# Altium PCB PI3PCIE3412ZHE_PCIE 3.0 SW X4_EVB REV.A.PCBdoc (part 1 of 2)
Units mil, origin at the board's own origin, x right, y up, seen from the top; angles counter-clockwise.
Board outline 3399 x 2712 mil, 8 copper layers (TopLayer, InternalPlane1, MidLayer1, MidLayer2, MidLayer3, MidLayer4, InternalPlane2, BottomLayer); 24 components, 100 nets, 589 pads, 111 vias.
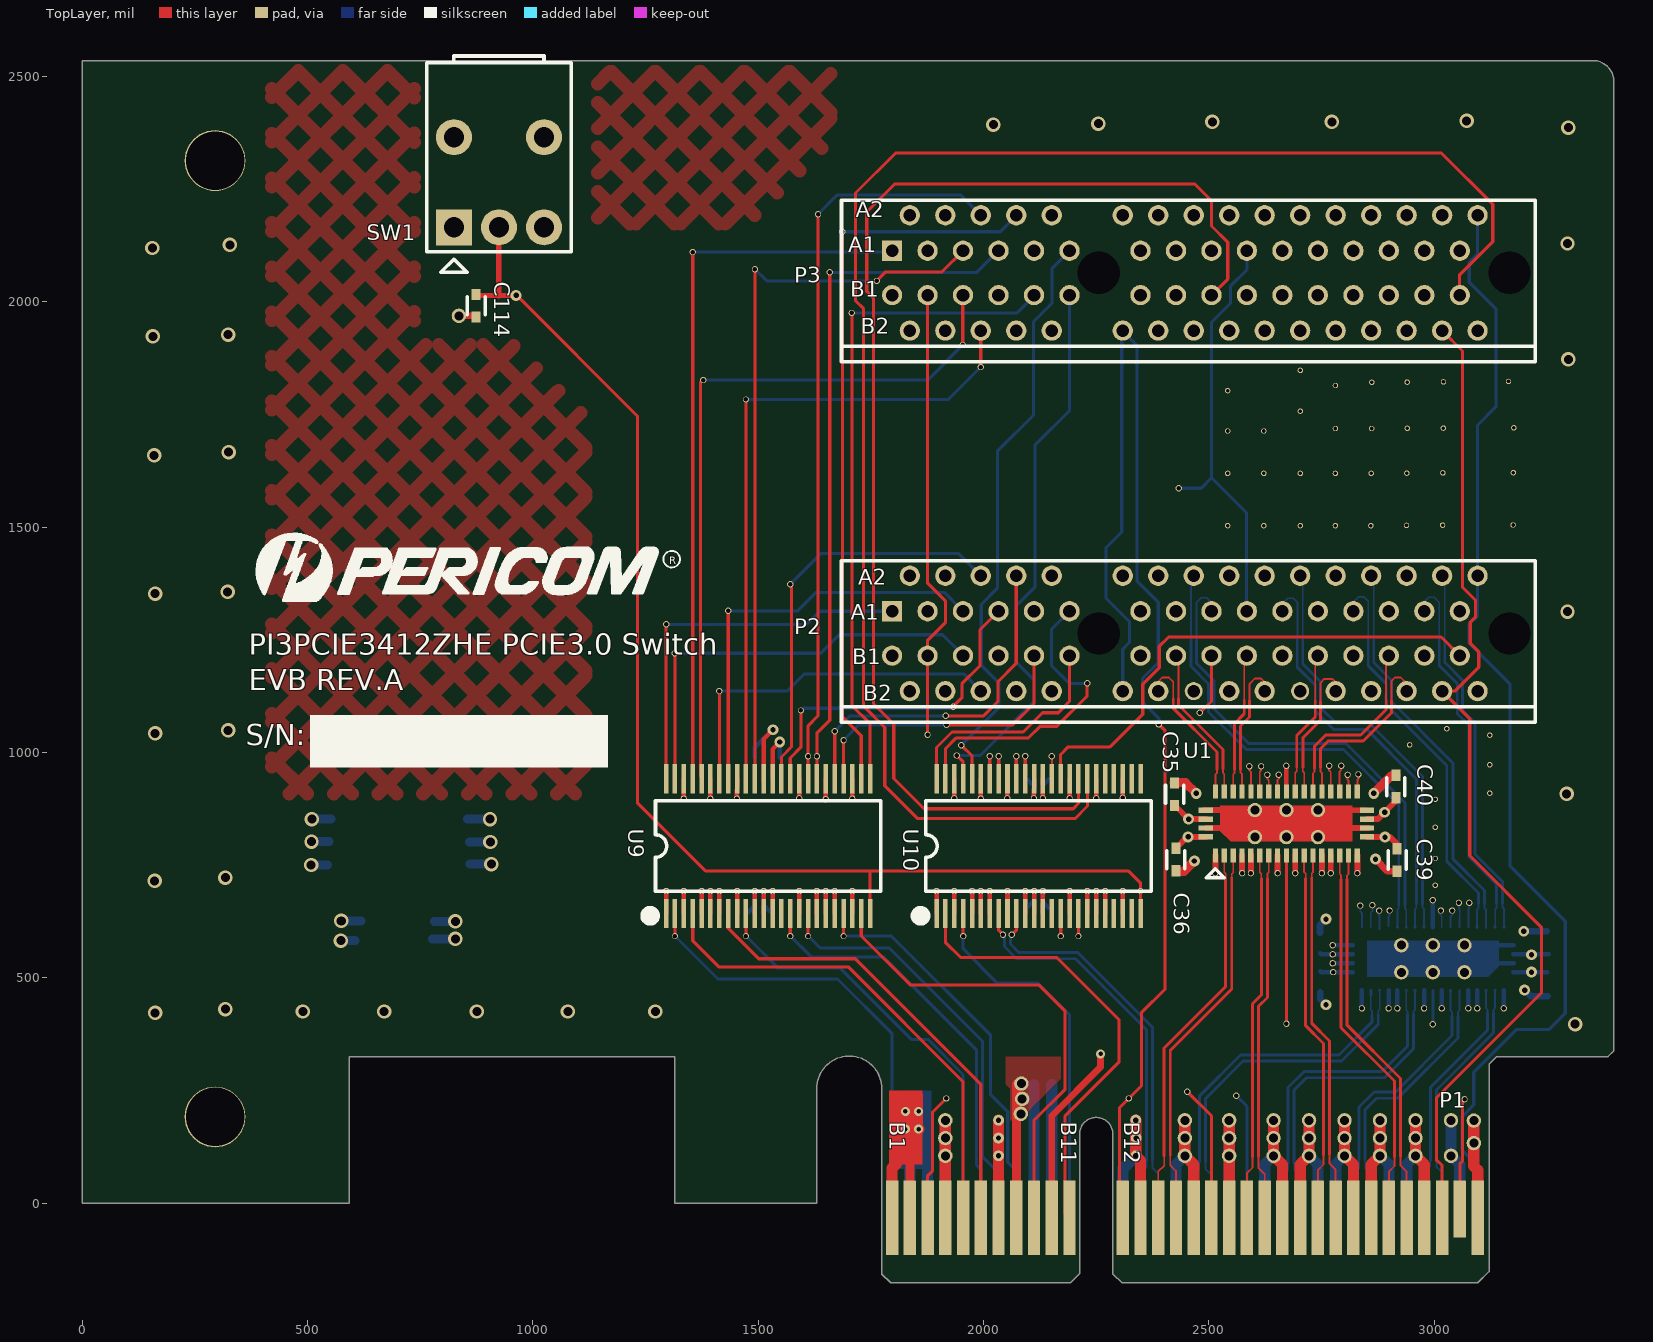
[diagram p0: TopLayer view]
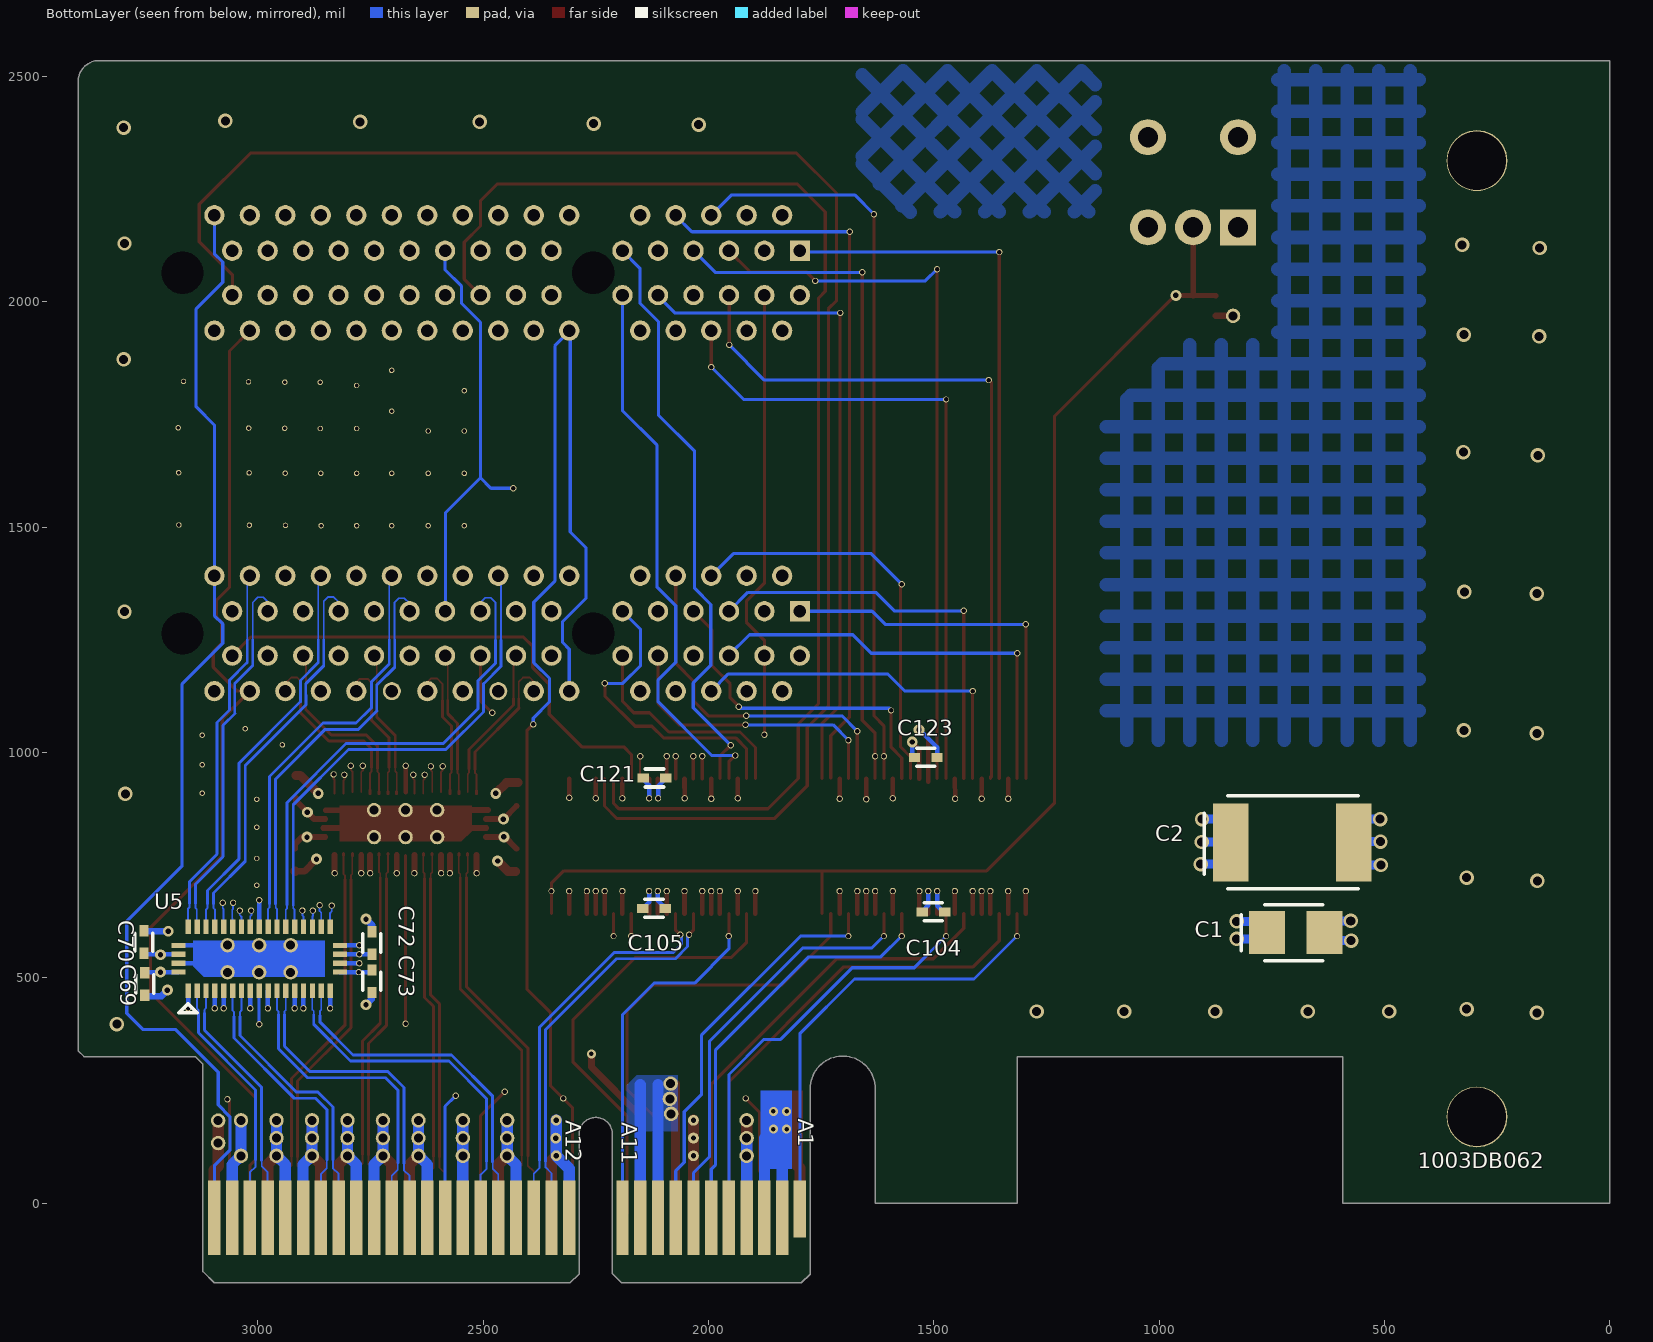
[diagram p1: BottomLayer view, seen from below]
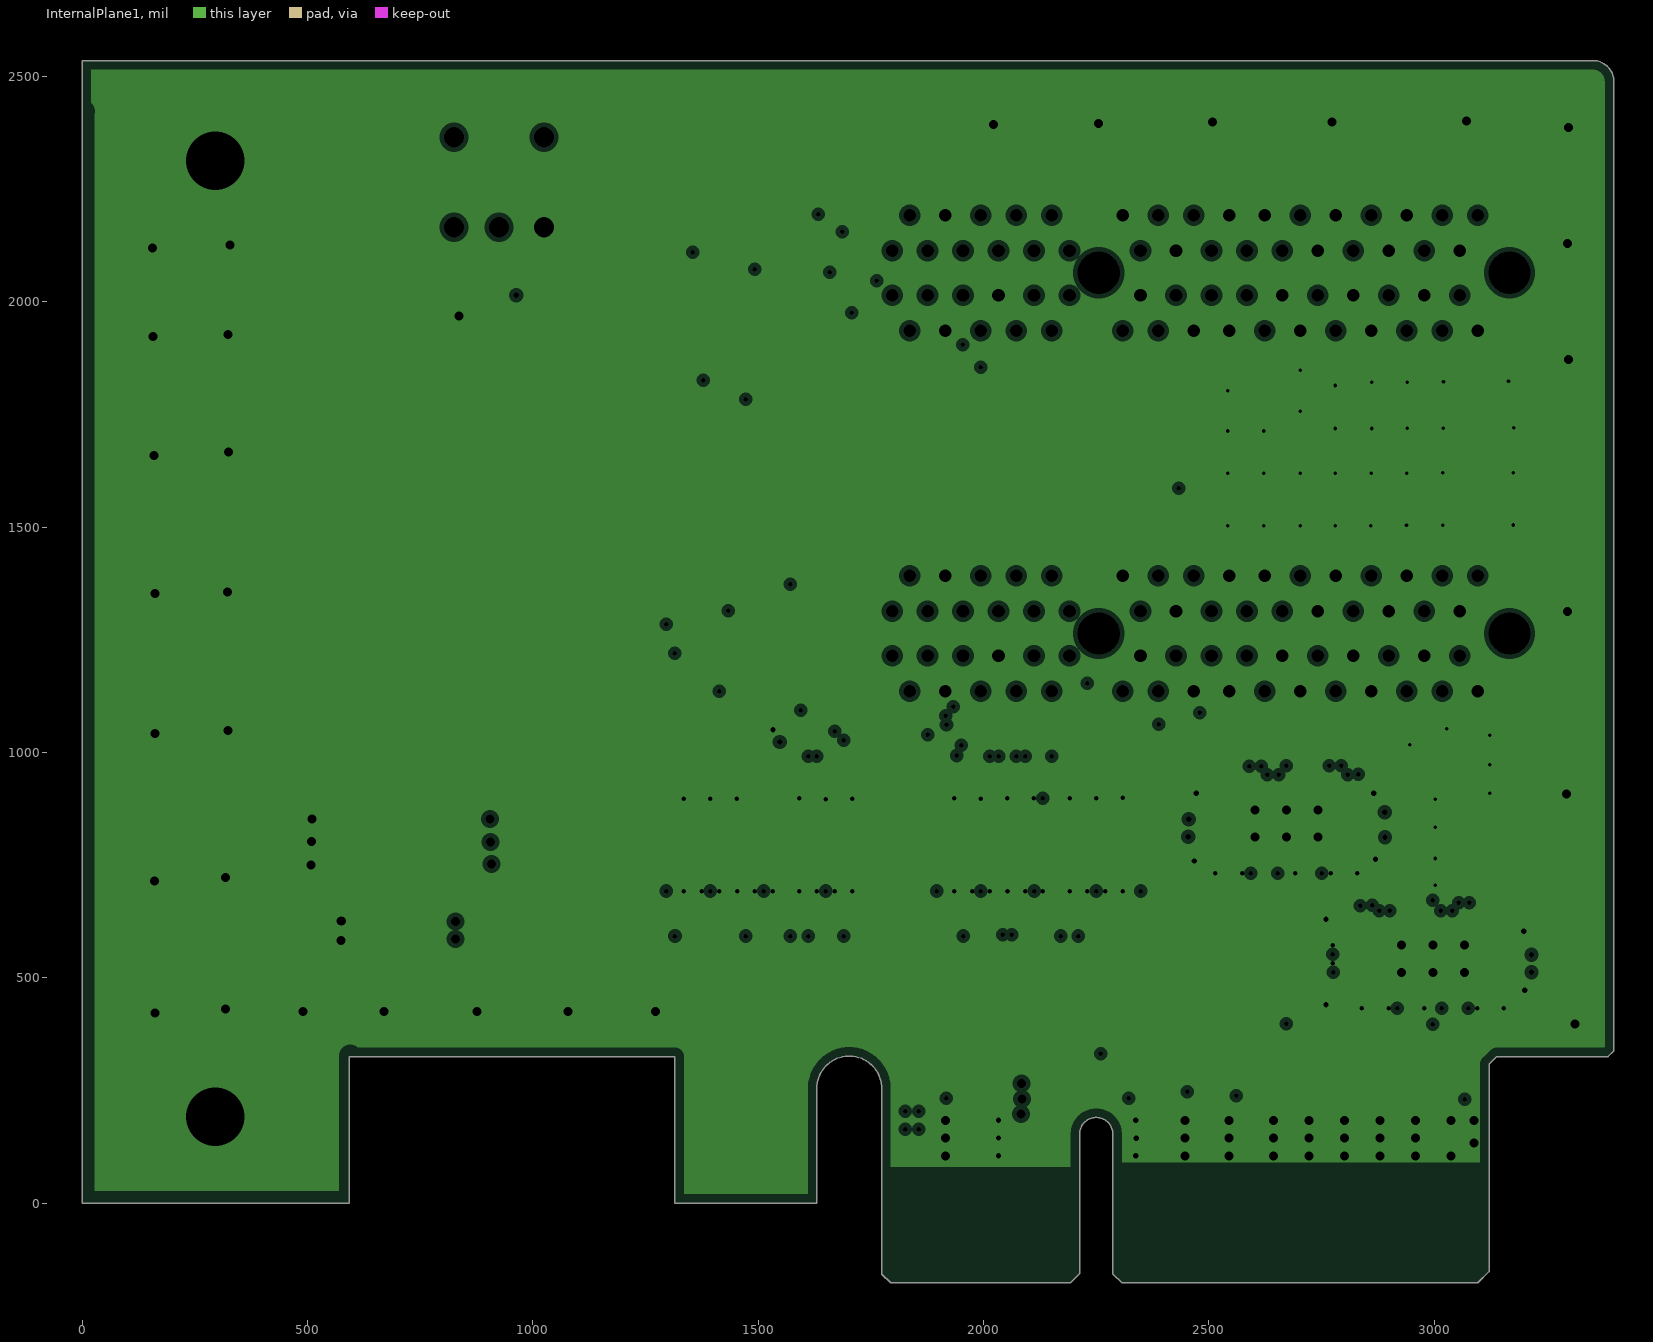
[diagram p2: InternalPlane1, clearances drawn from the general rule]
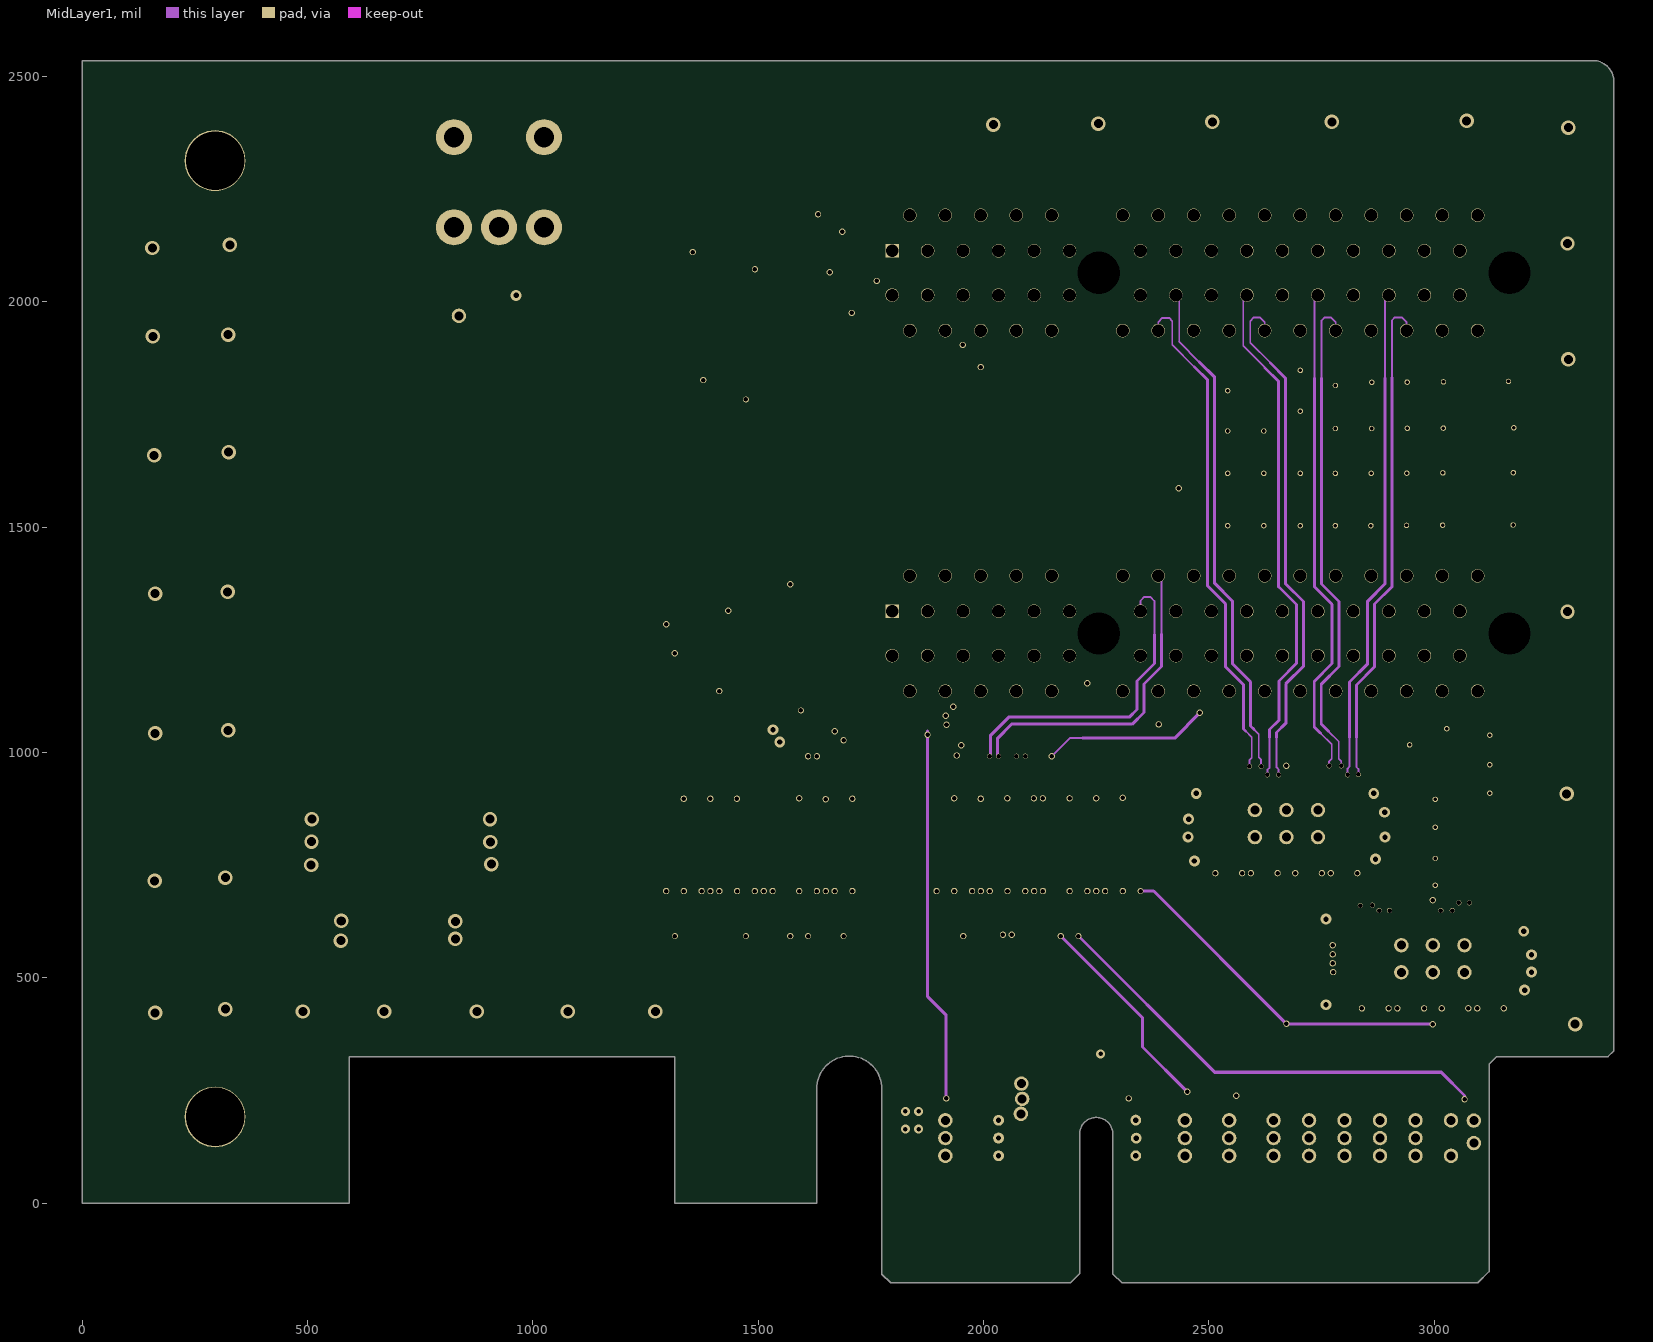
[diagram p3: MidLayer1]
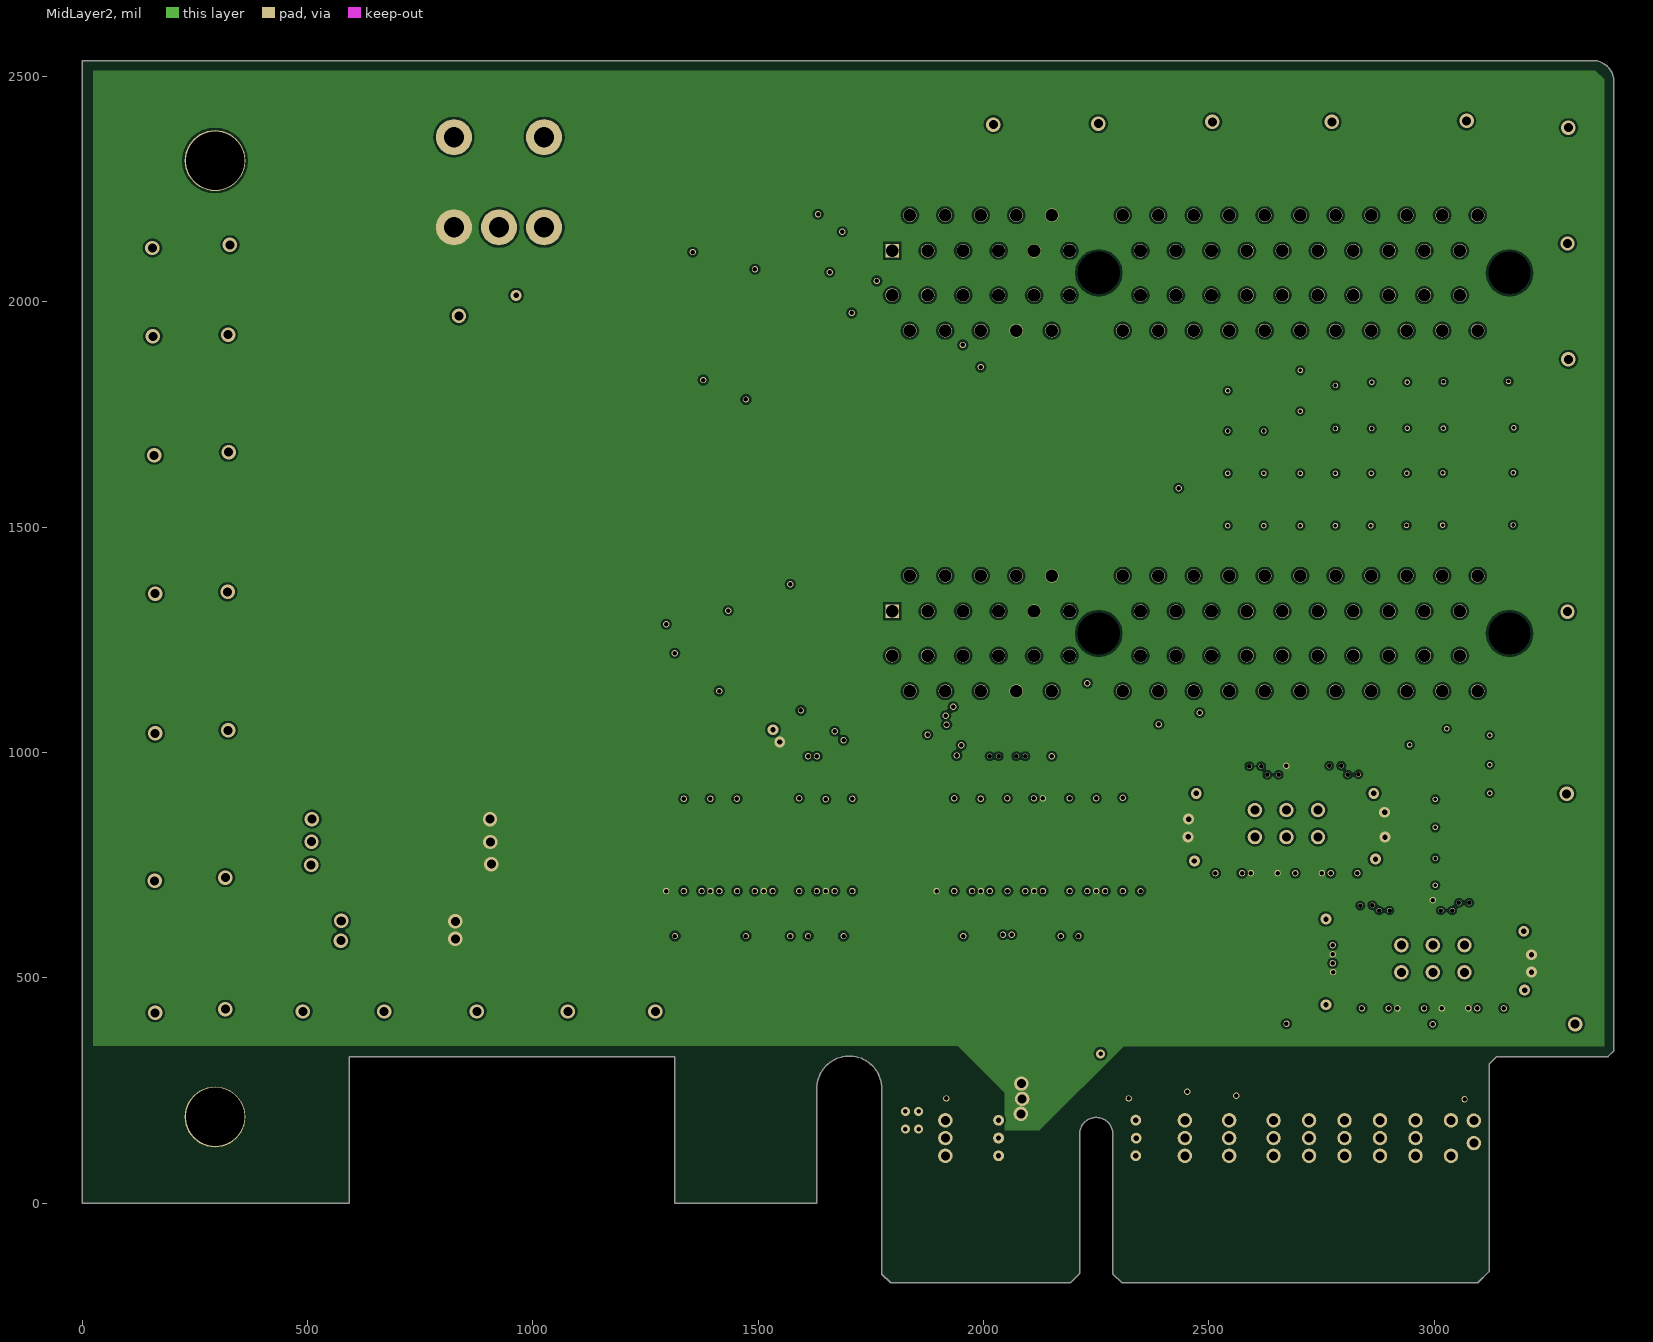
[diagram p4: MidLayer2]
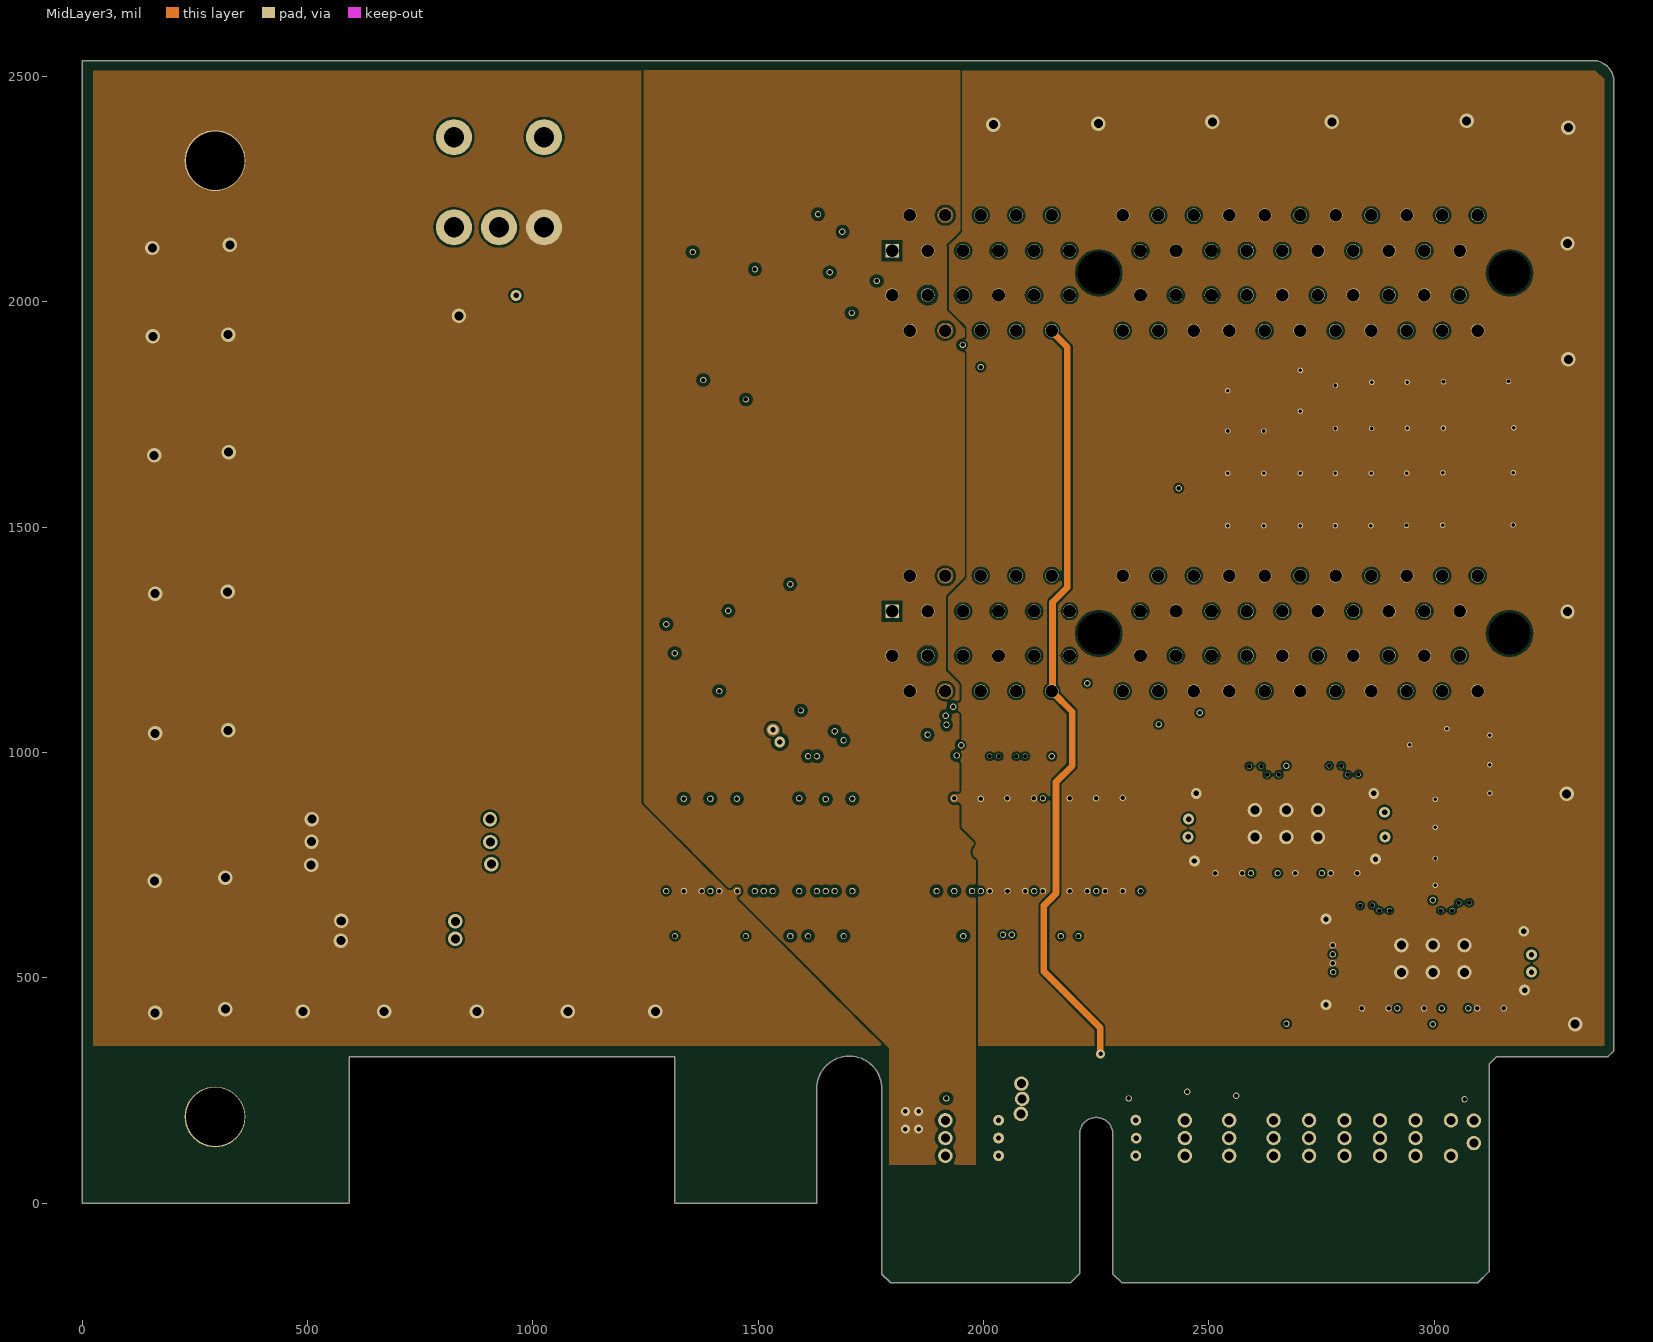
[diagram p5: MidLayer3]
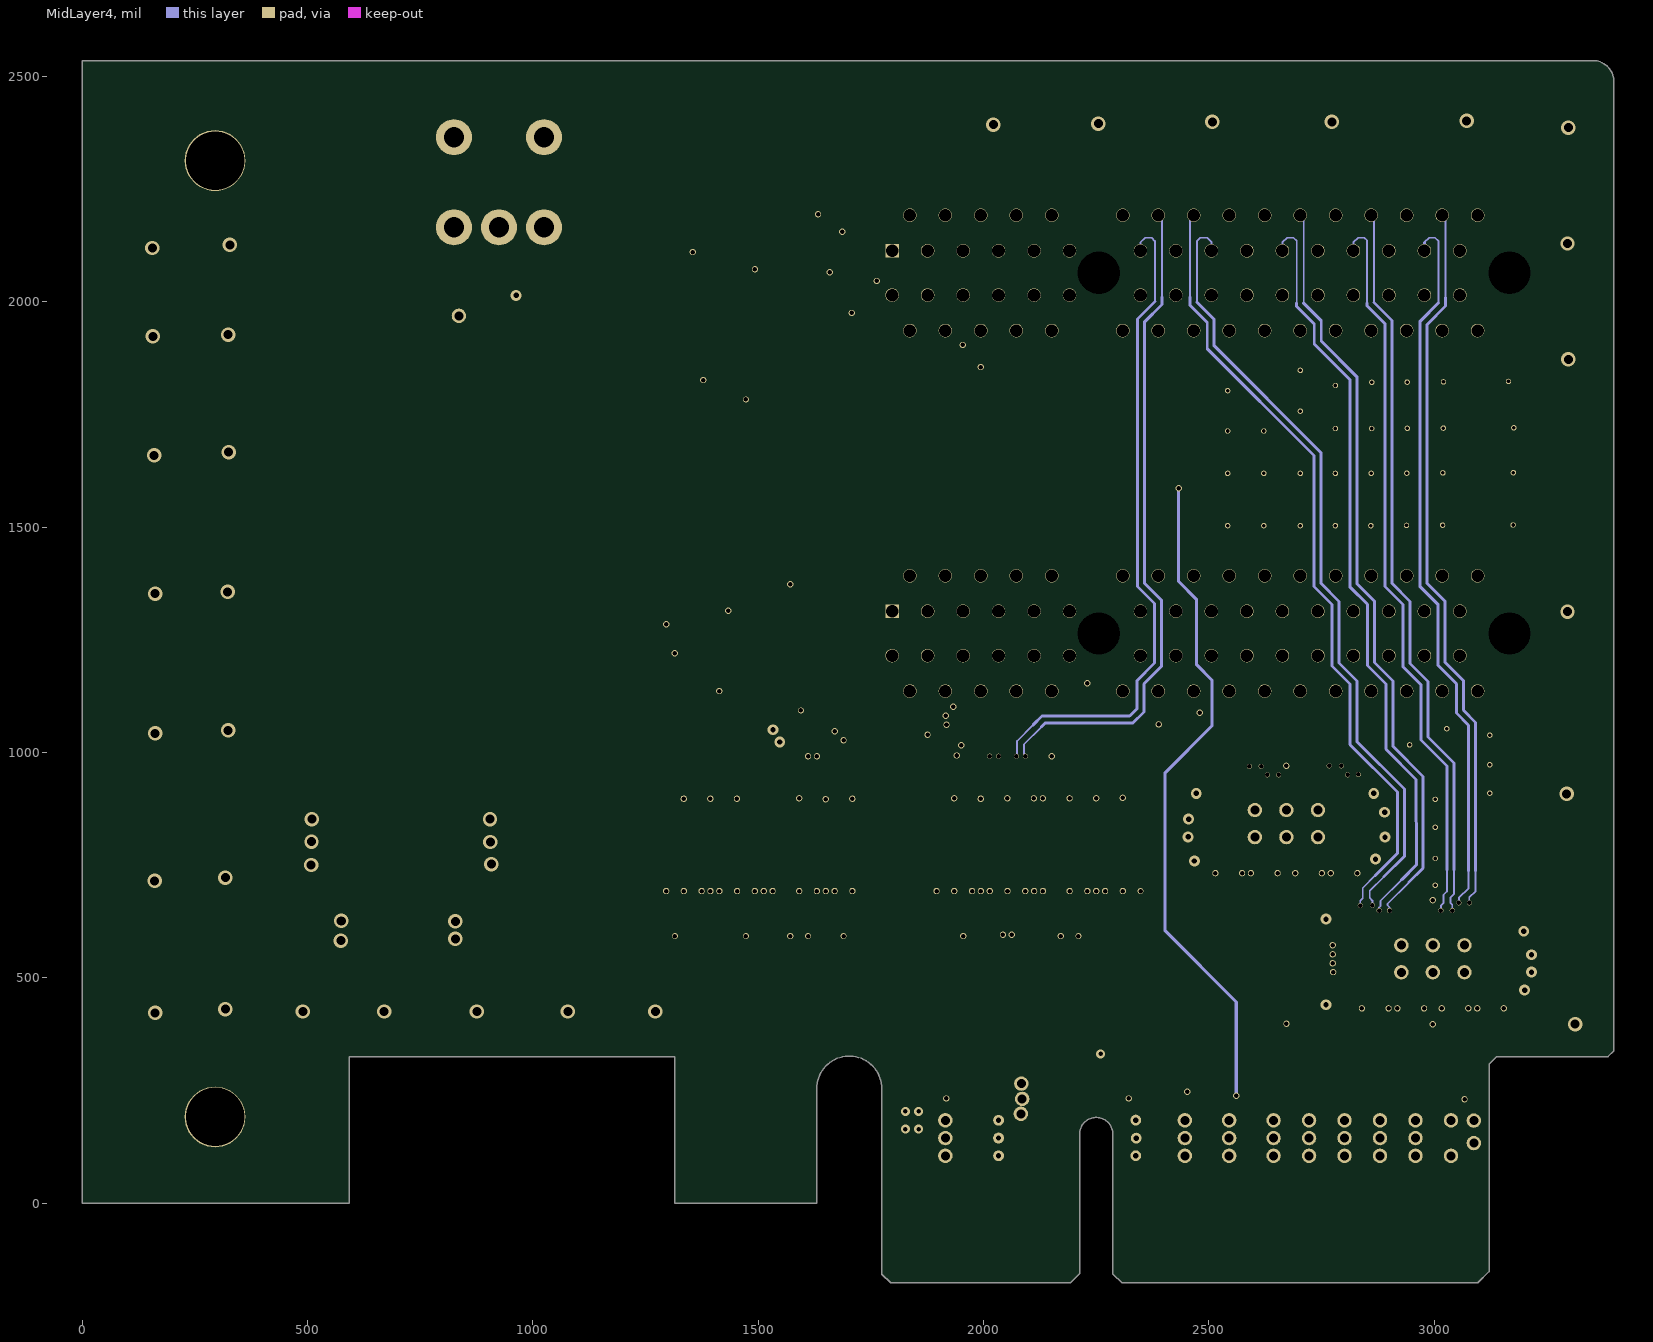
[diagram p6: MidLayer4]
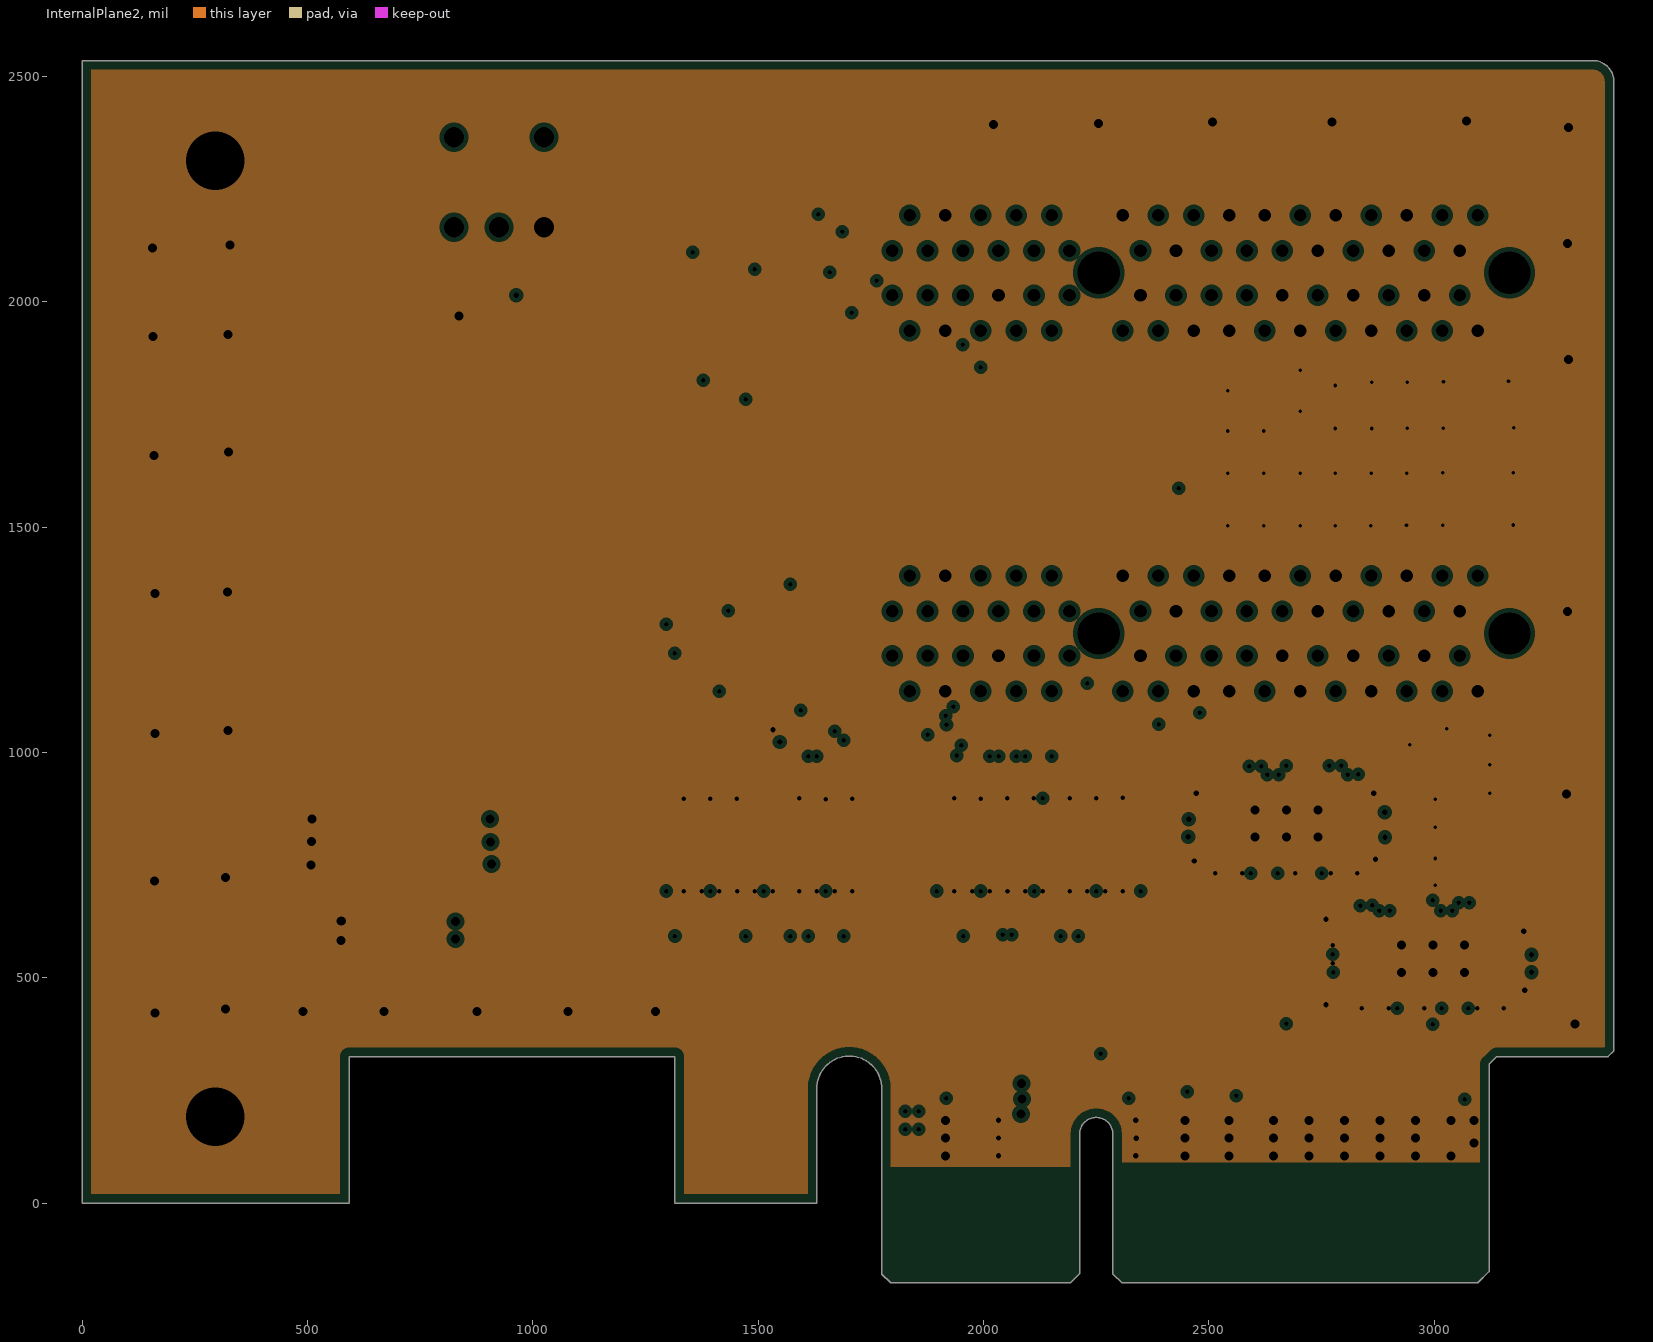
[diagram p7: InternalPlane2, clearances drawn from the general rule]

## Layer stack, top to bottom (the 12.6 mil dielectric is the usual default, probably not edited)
TopLayer: signal copper 1.4
Dielectric: core 12.6, FR-4, Dk 4.8
InternalPlane1: plane copper 1.4, net GND
Dielectric: prepreg 12.6, FR-4, Dk 4.8
MidLayer1: signal copper 1.4
Dielectric: core 12.6, FR-4, Dk 4.8
MidLayer2: signal copper 1.4
Dielectric: prepreg 12.6, FR-4, Dk 4.8
MidLayer3: signal copper 1.4
Dielectric: core 12.6, FR-4, Dk 4.8
MidLayer4: signal copper 1.4
Dielectric: prepreg 12.6, FR-4, Dk 4.8
InternalPlane2: plane copper 1.4, net GND
Dielectric: core 12.6, FR-4, Dk 4.8
BottomLayer: signal copper 1.4

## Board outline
1794.24,-177 1774.24,-158 1774.24,254 ccw(c1702.24,254) 1630.24,254 1630.24,0 1315.24,0 1315.24,325 592.24,325 592.24,0 0,0 0,2535 3353,2535 cw(c3352,2488) 3399,2487 3399,338 3385.99,324.99 3385.99,325 3139,325 3121.99,307.99 3121.99,-152 3122,-152 3097,-177 2307.24,-177 2287.24,-158 2287.24,153 ccw(c2250.24,153) 2213.24,153 2213.24,-157 2193.24,-177

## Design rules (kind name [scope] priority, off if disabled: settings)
Clearance [InNetClass('gap7')] p1: gap=5
Clearance Clearance_3 [OnLayer('BottomLayer') vs OnLayer('BottomLayer')] p2: gap=5.8
Clearance Clearance_2 [OnLayer('TopLayer') vs OnLayer('TopLayer')] p3: gap=5.8
Clearance Clearance_1 [All] p4: gap=5
ComponentClearance [All] p1: gap=10 collisioncheckmode=2 verticalgap=10
DiffPairsRouting [All] p1: maxlimit=6 minlimit=6 mostfreqgap=6 maxuncoupledlength=500
HoleSize [All] p1: absolutevalues=TRUE maxlimit=300 minlimit=1 maxpercent=80.000 minpercent=20.000
MatchedLengths MatchedLengths_1 [InNetClass('REFCLK') vs InFromToClass('')] p1: tolerance=50 checknetsindiffpair=TRUE checkdiffpairvsdiffpair=TRUE checkothers=TRUE
MatchedLengths [InNetClass('S_CLK') vs InFromToClass('')] p2: tolerance=50 checknetsindiffpair=TRUE checkdiffpairvsdiffpair=TRUE checkothers=TRUE
MinimumAnnularRing [All] p1 off: minimumring=0.5
PlaneClearance [All] p1: clearance=10
PlaneConnect PlaneConnect_2 [HasPad('Free-0')] p1: planeconnectstyle=Direct reliefexpansion=20 reliefentries=4 reliefconductorwidth=10 reliefairgap=10
PlaneConnect PlaneConnect_1 [HasPad('Free-998')] p2: planeconnectstyle=Direct reliefexpansion=20 reliefentries=4 reliefconductorwidth=10 reliefairgap=10
PlaneConnect PlaneConnect_3 [All] p3: planeconnectstyle=Direct reliefexpansion=20 reliefentries=4 reliefconductorwidth=10 reliefairgap=10
PlaneConnect [All] p4: planeconnectstyle=Direct reliefexpansion=10 reliefentries=4 reliefconductorwidth=12 reliefairgap=6
PolygonConnect [All] p1: connectstyle=Direct reliefconductorwidth=10 reliefentries=4 polygonreliefangle="90 Angle"
RoomDefinition "P05-PI3DBV40 SW" [InComponentClass('P05-PI3DBV40 SW')] p1: confinementstyle=ConfineIn formatcopy=TRUE lockcomponents=FALSE outline -6697.46,-11297.6 -4697.46,-11297.6 -4697.46,-10297.6 -6697.46,-10297.6
RoomDefinition "P04-PI3PCIE3412ZHE SW" [InComponentClass('P04-PI3PCIE3412ZHE SW')] p2: confinementstyle=ConfineIn formatcopy=TRUE lockcomponents=FALSE outline -6697.46,-11297.6 -4697.46,-11297.6 -4697.46,-10297.6 -6697.46,-10297.6
RoomDefinition P03-PCI_EXPRESS_CONNx4 [InComponentClass('P03-PCI_EXPRESS_CONNx4')] p3: confinementstyle=ConfineIn formatcopy=TRUE lockcomponents=FALSE outline -6697.46,-11297.6 -4697.46,-11297.6 -4697.46,-10297.6 -6697.46,-10297.6
RoomDefinition P02-PCI_EDGE_CONNx4 [InComponentClass('P02-PCI_EDGE_CONNx4')] p4: confinementstyle=ConfineIn formatcopy=TRUE lockcomponents=FALSE outline -6697.46,-11297.6 -4697.46,-11297.6 -4697.46,-10297.6 -6697.46,-10297.6
RoutingVias [All] p1: holewidth=28 width=50 viastyle="Through Hole" minholewidth=8 minwidth=10 maxholewidth=28 maxwidth=50
SolderMaskExpansion SolderMaskExpansion_2 [HasPad('Free-998')] p1: expansion=-6
SolderMaskExpansion SolderMaskExpansion_3 [HasPad('Free-0')] p2: expansion=-10
SolderMaskExpansion SolderMaskExpansion_1 [(IsWire) Or (IsVia) Or (IsFill)] p3: expansion=-6
SolderMaskExpansion [All] p4: expansion=2.5
TestPointUsage [All] p1: valid=0 allowmultiple=FALSE
Testpoint [All] p1: side=15 testpointundercomponent=TRUE minsize=40 maxsize=100 preferedsize=60 minholesize=20 maxholesize=40 preferedholesize=32 testpointgrid=1 style=1023 order=0123456789
UnRoutedNet UnRoutedNet_2 [All] p1:
Width [InNetClass('diff')] p1: maxlimit=50 minlimit=4 preferedwidth=6.5
Width Width_2 [InNetClass('PWR')] p2: maxlimit=50 minlimit=4 preferedwidth=10
Width Width_1 [All] p3: maxlimit=70 minlimit=4 preferedwidth=7
13 further rules are at their usual default settings.

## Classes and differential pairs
component class "P05-PI3DBV40 SW": C104 C105 C114 C121 C123 SW1 U9 U10
component class P03-PCI_EXPRESS_CONNx4: P2 P3
component class P02-PCI_EDGE_CONNx4: C1 C2 P1
component class "P04-PI3PCIE3412ZHE SW": C34 C35 C36 C37 C38 C39 C40 C41 C66 C67 C68 C69 C70 C71 C72 C73 U1 U5

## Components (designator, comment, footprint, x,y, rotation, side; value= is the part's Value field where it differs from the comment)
C1 "10u_3528" CT_3528 697,600 r180 bottom
C2 "47u_7343" CT_7343 723,800 r0 bottom
C35 "0.1u_0402" CC_0402 2424,907 r90 top
C36 "0.1u_0402" CC_0402 2427,762 r270 top
C39 "0.1u_0402" CC_0402 2918,761 r270 top
C40 "0.1u_0402" CC_0402 2915,924 r90 top
C69 "0.1u_0402" CC_0402 3251,486 r270 bottom
C70 "0.1u_0402" CC_0402 3253,579 r90 bottom
C72 "0.1u_0402" CC_0402 2747.24,577 r90 bottom
C73 "0.1u_0402" CC_0402 2747.24,492 r270 bottom
C104 "0.1u_0402" CC_0402 1501,646 r180 bottom
C105 "0.1u_0402" CC_0402 2121,654 r0 bottom
C114 "0.1u_0402" CC_0402 874.24,1991 r270 top
C121 "0.1u_0402" CC_0402 2120,943 r180 bottom
C123 "0.1u_0402" CC_0402 1518,989 r180 bottom
P1 "CON_PCIex4_Finger" CON_PCIex4_Finger 1797.24,-33 r0 top
P2 "CON_PCIex4_Edge_Recept" CON_PCIEX4_RECEPT#1 1797.24,1312.99 r0 top
P3 "CON_PCIex4_Edge_Recept" CON_PCIEX4_RECEPT#2 1797.24,2112.99 r0 top
SW1 "SW_SPDT_Toggle_RT" SWSPDT 825,2165 r180 top
U1 "PI3PCIE3412@TQFN42" TQFN42 2672.24,842 r0 top
U5 "PI3PCIE3412@TQFN42" TQFN42 2997,542 r180 bottom
U9 "PI3DBV40@WTSSOP48" WTSSOP48 1522.24,792 r90 top
U10 "PI3DBV40@WTSSOP48" WTSSOP48 2122.24,792 r90 top
? "" PSC_LOG 494,1440 r0 top

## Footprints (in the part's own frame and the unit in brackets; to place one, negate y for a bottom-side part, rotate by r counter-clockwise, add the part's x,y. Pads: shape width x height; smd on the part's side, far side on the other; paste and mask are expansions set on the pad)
CC_0402 [mil]
  rect 25x20 smd: 1(-25,0) 2(25,0)
  silkscreen extent -20,-20 20,20
CON_PCIex4_Finger [mm]
  rect 0.7x3.2 smd far side: A1(0,0.5)
  rect 0.7x4.2 smd far side: A2(1,0) A3(2,0) A4(3,0) A5(4,0) A6(5,0) A7(6,0) A8(7,0) A9(8,0) A10(9,0) A11(10,0) A12(13,0) A13(14,0) A14(15,0) A15(16,0) A16(17,0) A17(18,0) A18(19,0) A19(20,0) A20(21,0) A21(22,0) A22(23,0) A23(24,0) A24(25,0) A25(26,0) A26(27,0) A27(28,0) A28(29,0) A29(30,0) A30(31,0) A31(32,0) A32(33,0)
  rect 0.7x4.2 smd: B1(0,0) B2(1,0) B3(2,0) B4(3,0) B5(4,0) B6(5,0) B7(6,0) B8(7,0) B9(8,0) B10(9,0) B11(10,0) B12(13,0) B13(14,0) B14(15,0) B15(16,0) B16(17,0) B17(18,0) B18(19,0) B19(20,0) B20(21,0) B21(22,0) B22(23,0) B23(24,0) B24(25,0) B25(26,0) B26(27,0) B27(28,0) B28(29,0) B29(30,0) B30(31,0) B32(33,0)
  rect 0.7x3.2 smd: B31(32,0.5)
CON_PCIEX4_RECEPT#1 [mil]
  round 0 hole 94.02 unplated: 165(458.65,-49.21) 166(1370.08,-49.22)
  rect 45x45 / inner rect 30x30 / far side rect 45x45 hole 28: A1(0,0)
  round 45 / inner round 30 / far side round 45 hole 28: A2(39.37,78.74) A3(78.74,0) A4(118.11,78.74) A5(157.48,0) A6(196.85,78.74) A7(236.22,0) A8(275.59,78.74) A9(314.96,0) A10(354.33,78.74) A11(393.7,0) A12(511.81,78.74) A13(551.18,0) A14(590.55,78.74) A15(629.92,0) A16(669.29,78.74) A17(708.66,0) A18(748.03,78.74) A19(787.4,0) A20(826.77,78.74) A21(866.14,0) A22(905.51,78.74) A23(944.88,0) A24(984.25,78.74) A25(1023.62,0) A26(1062.99,78.74) A27(1102.36,0) A28(1141.73,78.74) A29(1181.1,0) A30(1220.47,78.74) A31(1259.84,0) A32(1299.21,78.74) B1(0,-98.42) B2(39.37,-177.16) B3(78.74,-98.42) B4(118.11,-177.16) B5(157.48,-98.42) B6(196.85,-177.16) B7(236.22,-98.42) B8(275.59,-177.16) B9(314.96,-98.42) B10(354.33,-177.16) B11(393.7,-98.42) B12(511.81,-177.16) B13(551.18,-98.42) B14(590.55,-177.16) B15(629.92,-98.42) B17(708.66,-98.42) B18(748.03,-177.16) B19(787.4,-98.42) B20(826.77,-177.16) B21(866.14,-98.42) B23(944.88,-98.42) B24(984.25,-177.16) B25(1023.62,-98.42) B26(1062.99,-177.16) B27(1102.36,-98.42) B28(1141.73,-177.16) B29(1181.1,-98.42) B30(1220.47,-177.16) B31(1259.84,-98.42) B32(1299.21,-177.16)
  round 40 / inner round 30 / far side round 40 hole 28: B16(669.29,-177.16) B22(905.51,-177.16)
  silkscreen extent -112,-246 1427,112
CON_PCIEX4_RECEPT#2 [mil]
  round 0 hole 94.02 unplated: 165(458.65,-49.21) 166(1370.08,-49.21)
  rect 45x45 / inner rect 30x30 / far side rect 45x45 hole 28: A1(0,0)
  round 45 / inner round 30 / far side round 45 hole 28: A2(39.37,78.74) A3(78.74,0) A4(118.11,78.74) A5(157.48,0) A6(196.85,78.74) A7(236.22,0) A8(275.59,78.74) A9(314.96,0) A10(354.33,78.74) A11(393.7,0) A12(511.81,78.74) A13(551.18,0) A14(590.55,78.74) A15(629.92,0) A16(669.29,78.74) A17(708.66,0) A18(748.03,78.74) A19(787.4,0) A20(826.77,78.74) A21(866.14,0) A22(905.51,78.74) A23(944.88,0) A24(984.25,78.74) A25(1023.62,0) A26(1062.99,78.74) A27(1102.36,0) A28(1141.73,78.74) A29(1181.1,0) A30(1220.47,78.74) A31(1259.84,0) A32(1299.21,78.74) B1(0,-98.42) B2(39.37,-177.16) B3(78.74,-98.42) B4(118.11,-177.16) B5(157.48,-98.42) B6(196.85,-177.16) B7(236.22,-98.42) B8(275.59,-177.16) B9(314.96,-98.42) B10(354.33,-177.16) B11(393.7,-98.42) B12(511.81,-177.16) B13(551.18,-98.42) B14(590.55,-177.16) B15(629.92,-98.42) B16(669.29,-177.16) B17(708.66,-98.42) B18(748.03,-177.16) B19(787.4,-98.42) B20(826.77,-177.16) B21(866.14,-98.42) B22(905.51,-177.16) B23(944.88,-98.42) B24(984.25,-177.16) B25(1023.62,-98.42) B26(1062.99,-177.16) B27(1102.36,-98.42) B28(1141.73,-177.16) B29(1181.1,-98.42) B30(1220.47,-177.16) B31(1259.84,-98.42) B32(1299.21,-177.16)
  silkscreen extent -112,-246 1427,112
CT_3528 [mil]
  rect 80x95 smd: 1(-64,0) 2(64,0)
  silkscreen extent -121,-62 60,62
CT_7343 [mm]
  rect 2x4.4 smd: 1(3,0) 2(-3.926,-0.011)
  silkscreen extent -4.19,-2.64 4.5,2.62
PSC_LOG [mil]
  silkscreen extent -107,-103 833,45
SWSPDT [mil]
  rect 80x80 / inner round 80 / far side rect 80x80 hole 45: 1(0,0)
  round 80 hole 45: 2(-100,0) 3(-200,0) 4(-200,-200) 5(0,-200)
  silkscreen extent -260,-380 60,100
TQFN42 [mm]
  rect 0.3x0.8 smd: 1(-4,-1.8) 2(-3.5,-1.8) 3(-3,-1.8) 4(-2.5,-1.8) 5(-2.007,-1.8) 6(-1.5,-1.8) 7(-1,-1.8) 8(-0.5,-1.8) 9(0,-1.8) 10(0.5,-1.8) 11(1,-1.8) 12(1.5,-1.8) 13(2,-1.8) 14(2.5,-1.8) 15(3,-1.8) 16(3.5,-1.8) 17(4,-1.8) 22(4,1.8) 23(3.5,1.8) 24(3,1.8) 25(2.5,1.8) 26(2.007,1.8) 27(1.5,1.8) 28(1,1.8) 29(0.5,1.8) 30(0,1.8) 31(-0.5,1.8) 32(-1,1.8) 33(-1.5,1.8) 34(-2,1.8) 35(-2.5,1.8) 36(-3,1.8) 37(-3.5,1.8) 38(-4,1.8)
  rect 0.8x0.3 smd: 18(4.55,-0.75) 19(4.55,-0.25) 20(4.55,0.25) 21(4.55,0.75) 39(-4.55,0.75) 40(-4.55,0.25) 41(-4.55,-0.25) 42(-4.55,-0.75)
  TopLayer region: -3.72,1.01 3.7,1.01 3.7,-1.01 -3.14,-1.01 -3.72,-0.43
  silkscreen extent -4.52,-3.05 -3.51,-2.54
WTSSOP48 [mil]
  rect 65x10 smd: 1(-149.61,226.38) 2(-149.61,206.69) 3(-149.61,187.01) 4(-149.61,167.32) 5(-149.61,147.64) 6(-149.61,127.95) 7(-149.61,108.27) 8(-149.61,88.58) 9(-149.61,68.9) 10(-149.61,49.21) 11(-149.61,29.53) 12(-149.61,9.84) 13(-149.61,-9.84) 14(-149.61,-29.53) 15(-149.61,-49.21) 16(-149.61,-68.9) 17(-149.61,-88.58) 18(-149.61,-108.27) 19(-149.61,-127.95) 20(-149.61,-147.64) 21(-149.61,-167.32) 22(-149.61,-187.01) 23(-149.61,-206.69) 24(-149.61,-226.38) 25(149.61,-226.38) 26(149.61,-206.69) 27(149.61,-187.01) 28(149.61,-167.32) 29(149.61,-147.64) 30(149.61,-127.95) 31(149.61,-108.27) 32(149.61,-88.58) 33(149.61,-68.9) 34(149.61,-49.21) 35(149.61,-29.53) 36(149.61,-9.84) 37(149.61,9.84) 38(149.61,29.53) 39(149.61,49.21) 40(149.61,68.9) 41(149.61,88.58) 42(149.61,108.27) 43(149.61,127.95) 44(149.61,147.64) 45(149.61,167.32) 46(149.61,187.01) 47(149.61,206.69) 48(149.61,226.38)
  silkscreen extent -165,-250 100,272

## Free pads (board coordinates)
  round 20 on Drill Guide: 0(1,-177)
  round 135 hole 130: 0(295,191) 0(295,2313)
  round 32 hole 20: 0(836.11,1968.5) 0(1915.35,104.8) 0(1915.35,144.16) 0(1915.35,183.54) 0(2083,198) 0(2084,265) 0(2086,231) 0(2446.85,104.8) 0(2446.85,144.16) 0(2446.85,183.54) 0(2545.28,104.8) 0(2545.28,144.16) 0(2545.28,183.54) 0(2602.24,812) 0(2602.24,872) 0(2643.7,104.8) 0(2643.7,144.16) 0(2643.7,183.54) 0(2672.24,812) 0(2672.24,872) 0(2722.44,104.8) 0(2722.44,144.16) 0(2722.44,183.54) 0(2742.24,812) 0(2742.24,872) 0(2801.18,104.8) 0(2801.18,144.16) 0(2801.18,183.54) 0(2879.92,104.8) 0(2879.92,144.16) 0(2879.92,183.54) 0(2927.24,512) 0(2927.24,572) 0(2958.66,104.8) 0(2958.66,144.16) 0(2958.66,183.54) 0(2997.24,512) 0(2997.24,572) 0(3037.45,104.8) 0(3037.45,183.49) 0(3067.24,512) 0(3067.24,572) 0(3088,133) 0(3088,183)
  round 24 hole 12: 0(2033.46,104.8) 0(2033.46,144.16) 0(2033.46,183.54) 0(2338,105) 0(2338,184) 0(2339,144)
  round 12 hole 8: 0(2542,1503) 0(2542,1619) 0(2542,1713) 0(2542,1802.5) 0(2622,1503) 0(2622,1619) 0(2622,1713) 0(2703,1503) 0(2703,1619) 0(2703,1757) 0(2703,1847.5) 0(2781,1503) 0(2781,1619) 0(2781,1718.5) 0(2781,1814) 0(2859.72,1503) 0(2860.43,1619) 0(2861.43,1718.5) 0(2861.72,1821) 0(2938.72,1503.5) 0(2939.43,1619.5) 0(2940.22,1821.5) 0(2940.43,1719) 0(2945.5,1016.5) 0(3002.5,705) 0(3002.5,764.5) 0(3002.5,833.5) 0(3002.5,895.5) 0(3018.72,1504) 0(3019.43,1620) 0(3020.43,1719.5) 0(3020.72,1822) 0(3028,1052.5) 0(3123.5,909.5) 0(3123.5,972.5) 0(3123.5,1038) 0(3165,1823) 0(3175.22,1504.5) 0(3175.93,1620.5) 0(3176.93,1720)
  round 14 / inner round 11 / far side round 14 hole 10: 1(2836,660) 2(2863,661) 3(2878,649) 4(2901,649) 5(3015,649) 6(3040,649) 7(3055,666) 8(3078,666) 9(2013.98,991.53) 10(2033.66,991.53) 11(2073.03,991.53) 12(2092.72,991.53) 13(2590,969) 14(2616,969) 15(2630,950) 16(2655,950) 17(2767,970) 18(2794,970) 19(2808,950) 20(2832,951)
  round 14 hole 10: 998(1295.87,692.32) 998(1335,897) 998(1335.24,692.32) 998(1374.61,692.32) 998(1394,897) 998(1394.29,692.32) 998(1413.98,692.32) 998(1453,897) 998(1453.35,692.32) 998(1492.72,692.32) 998(1512.4,692.32) 998(1532.09,692.32) 998(1591,898) 998(1591.14,692.32) 998(1630.51,692.32) 998(1650,896) 998(1650.2,692.32) 998(1669.88,692.32) 998(1709,897) 998(1709.25,692.32) 998(1895.87,692.32) 998(1935,898) 998(1935.24,692.32) 998(1974.61,692.32) 998(1994,897) 998(1994.29,692.32) 998(2013.98,692.32) 998(2053,898) 998(2053.35,692.32) 998(2092.72,692.32) 998(2112,898) 998(2112.4,692.32) 998(2132,898) 998(2132.09,692.32) 998(2191,898) 998(2191.14,692.32) 998(2230.51,692.32) 998(2250,898) 998(2250.2,692.32) 998(2269.88,692.32) 998(2309,899) 998(2309.25,692.32) 998(2389,1062) 998(2514.76,732) 998(2573.82,732) 998(2593.5,732) 998(2652.56,732) 998(2672,970) 998(2691.93,732) 998(2750.98,732) 998(2770.67,732) 998(2775,532) 998(2775,551.84) 998(2775,572) 998(2776,512.47) 998(2829.72,732) 998(2839.76,432) 998(2898.82,432) 998(2918.5,432) 998(2977.56,432) 998(2997,672) 998(3016.93,432) 998(3075.98,432) 998(3095.67,432) 998(3154.72,432)

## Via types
v1: diameter 14, hole 10, TopLayer to BottomLayer, tented both sides, 49 vias
v2: diameter 32, hole 20, TopLayer to BottomLayer, tented both sides, 40 vias
v3: diameter 24, hole 12, TopLayer to BottomLayer, tented both sides, 17 vias
v4: diameter 20, hole 10, TopLayer to BottomLayer, 5 vias

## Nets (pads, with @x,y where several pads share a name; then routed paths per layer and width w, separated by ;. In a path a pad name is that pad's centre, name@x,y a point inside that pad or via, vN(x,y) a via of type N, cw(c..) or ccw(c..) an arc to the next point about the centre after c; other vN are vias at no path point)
3.3VAUX: P1.B10 P2.B10 P3.B10 | length 2138.9
  TopLayer w15: P1.B10@2151.58,-33 2151.58,193.38 2259.84,301.65 v4(2259.84,331.17)
  MidLayer3 w15: P3.B10@2151.58,1935.83 2151.58,1933.42 2186,1899 2186,1366 2153,1333 2153,1134 2197,1090 2197,970 2161,934 2161,687 2134,660 2134,514 2259,389 v4@2259,330
+3.3V: C1.1 C2.1 C35.1 C36.1 C39.1 C40.1 C69.1 C70.1 C72.1 C73.1 C104.1 C105.1 C121.1 C123.1 P1.A9 P1.A10 P1.B8 P2.A9 P2.A10 P2.B8 P3.A9 P3.A10 P3.B8 pad.0@2083,198 pad.0@2084,265 pad.0@2086,231 pad.998@1295.87,692.32 pad.998@1394.29,692.32 pad.998@1512.4,692.32 pad.998@1650.2,692.32 pad.998@1895.87,692.32 pad.998@1994.29,692.32 pad.998@2112.4,692.32 pad.998@2132,898 pad.998@2250.2,692.32 pad.998@2593.5,732 pad.998@2652.56,732 pad.998@2672,970 pad.998@2750.98,732 pad.998@2775,551.84 pad.998@2776,512.47 pad.998@2918.5,432 pad.998@2997,672 pad.998@3016.93,432 pad.998@3075.98,432 SW1.1 U1.5 U1.8 U1.13 U1.18 U1.20 U1.30 U1.40 U1.42 U5.5 U5.8 U5.13 U5.18 U5.20 U5.30 U5.40 U5.42 U9.1 U9.6 U9.12 U9.19 U9.36 U10.1 U10.6 U10.12 U10.19 U10.36 | length 2829.6
  TopLayer w10: U9.1@1295.87,642.39 pad.998@1295.87,692.32 ; U9.6@1394.29,642.39 pad.998@1394.29,692.32 ; U9.12@1512.4,642.39 pad.998@1512.4,692.32 ; U9.36@1532.09,941.61 1532.09,1007.09 v3(1548,1023) ; U9.19@1650.2,642.39 pad.998@1650.2,692.32 ; U10.1@1895.87,642.39 pad.998@1895.87,692.32 ; U10.6@1994.29,642.39 pad.998@1994.29,692.32 ; U10.12@2112.4,642.39 pad.998@2112.4,692.32 ; pad.998@2132,898 U10.36@2132.09,941.61 ; U10.19@2250.2,642.39 pad.998@2250.2,692.32 ; pad.998@2672,970 U1.30@2672.24,911.88
  TopLayer w13: C36.1@2426,786 2452.47,812.47 U1.42@2494.09,812.47 ; C35.1@2426,881 v3(2455.16,851.84) U1.40@2494.09,851.84 ; pad.998@2593.5,732 U1.5@2593.5,772.12 ; pad.998@2652.56,732 U1.8@2652.56,772.12 ; pad.998@2750.98,732 U1.13@2750.98,772.12 ; U1.18@2850.39,812.47 2901.53,812.47 2918,796 C39.1@2918,786 ; U1.20@2850.39,851.84 2874.84,851.84 2915,892 C40.1@2915,899
  TopLayer w20: P1.B8@2072.83,-33 pad.0@2072.83,264.16
  BottomLayer w10: pad.998@1512.4,692.32 1512.4,660.6 C104.1@1525,648 ; C123.1@1548,988 v3(1548,1023) ; C105.1@2094,653 2112.4,671.4 pad.998@2112.4,692.32 ; pad.998@2132,898 2132,927 C121.1@2146,941 ; C73.1@2747.24,514.5 2749.27,512.47 U5.18@2819.09,512.47 ; C72.1@2747.24,554.5 2749.9,551.84 U5.20@2819.09,551.84 ; pad.998@2918.5,432 U5.13@2918.5,472.12 ; pad.998@2997,672 U5.30@2997.24,611.88 ; pad.998@3016.93,432 U5.8@3016.93,472.12 ; pad.998@3075.98,432 U5.5@3075.98,472.12 ; U5.42@3175.39,512.47 C69.1@3251,512.47 ; U5.40@3175.39,551.84 C70.1@3254,551.84
  BottomLayer w20: C1.1@777,586 v2(828,586) ; C1.1@782,625 v2(828,625) ; C2.1@855,852 v2(905,852) ; C2.1@860,801 v2(906,801) ; C2.1@861,752 v2(908,752)
  BottomLayer w25: P1.A9@2112.2,-33 2112.2,262.27 ; P1.A10@2151.58,-33 2151.58,262.27
  other v3: 3216,512.47 3216,551 2454,812.47 2891,812 2890,867
+12V: P1.A2 P1.A3 P1.B1 P1.B2 P2.A2 P2.A3 P2.B1 P2.B2 P3.A2 P3.A3 P3.B1 P3.B2 | length 991.6
  TopLayer w20: v4@1816.93,163.85 1816.93,239.78 ; P1.B2@1836.61,-33 v4@1836.61,163.85 ; v4(1856.3,163.85) 1856.3,239.78
  TopLayer w25: P1.B1@1797.24,-33 1797.24,77 1807.24,87 1807.24,144.32 v4(1826.77,163.85) ; 1836.61,144.16 1841.53,149.09 v4(1856.3,163.85)
  BottomLayer w25: v4(1826.77,163.85) 1836.61,154.01 P1.A2@1836.61,-33 ; v4(1856.3,163.85) 1875.98,144.16 P1.A3@1875.98,-33
  other v4: 1826.77,203.22 1856.3,203.22
GND: C1.2 C2.2 C35.2 C36.2 C39.2 C40.2 C69.2 C70.2 C72.2 C73.2 C104.2 C105.2 C114.2 C121.2 C123.2 P1.A4 P1.A12 P1.A15 P1.A18 P1.A20 P1.A23 P1.A24 P1.A27 P1.A28 P1.A31 P1.B4 P1.B7 P1.B13 P1.B16 P1.B18 P1.B21 P1.B22 P1.B25 P1.B26 P1.B29 P1.B32 P2.A4 P2.A12 P2.A15 P2.A18 P2.A20 P2.A23 P2.A24 P2.A27 P2.A28 P2.A31 P2.B4 P2.B7 P2.B13 P2.B16 P2.B18 P2.B21 P2.B22 P2.B25 P2.B26 P2.B29 P2.B32 P3.A4 P3.A12 P3.A15 P3.A18 P3.A20 P3.A23 P3.A24 P3.A27 P3.A28 P3.A31 P3.B4 P3.B7 P3.B13 P3.B16 P3.B18 P3.B21 P3.B22 P3.B25 P3.B26 P3.B29 P3.B32 pad.0@295,191 pad.0@295,2313 pad.0@836.11,1968.5 pad.0@1915.35,104.8 pad.0@1915.35,144.16 pad.0@1915.35,183.54 pad.0@2033.46,104.8 pad.0@2033.46,144.16 pad.0@2033.46,183.54 pad.0@2338,105 pad.0@2338,184 pad.0@2339,144 pad.0@2446.85,104.8 pad.0@2446.85,144.16 pad.0@2446.85,183.54 pad.0@2542,1503 pad.0@2542,1619 pad.0@2542,1713 pad.0@2542,1802.5 pad.0@2545.28,104.8 pad.0@2545.28,144.16 pad.0@2545.28,183.54 pad.0@2602.24,812 pad.0@2602.24,872 pad.0@2622,1503 pad.0@2622,1619 pad.0@2622,1713 pad.0@2643.7,104.8 pad.0@2643.7,144.16 pad.0@2643.7,183.54 pad.0@2672.24,812 pad.0@2672.24,872 pad.0@2703,1503 pad.0@2703,1619 pad.0@2703,1757 pad.0@2703,1847.5 pad.0@2722.44,104.8 pad.0@2722.44,144.16 pad.0@2722.44,183.54 pad.0@2742.24,812 pad.0@2742.24,872 pad.0@2781,1503 pad.0@2781,1619 pad.0@2781,1718.5 pad.0@2781,1814 pad.0@2801.18,104.8 pad.0@2801.18,144.16 pad.0@2801.18,183.54 pad.0@2859.72,1503 pad.0@2860.43,1619 pad.0@2861.43,1718.5 pad.0@2861.72,1821 pad.0@2879.92,104.8 pad.0@2879.92,144.16 pad.0@2879.92,183.54 pad.0@2927.24,512 pad.0@2927.24,572 pad.0@2938.72,1503.5 pad.0@2939.43,1619.5 pad.0@2940.22,1821.5 pad.0@2940.43,1719 pad.0@2945.5,1016.5 pad.0@2958.66,104.8 pad.0@2958.66,144.16 pad.0@2958.66,183.54 pad.0@2997.24,512 pad.0@2997.24,572 pad.0@3002.5,705 pad.0@3002.5,764.5 pad.0@3002.5,833.5 pad.0@3002.5,895.5 pad.0@3018.72,1504 pad.0@3019.43,1620 pad.0@3020.43,1719.5 pad.0@3020.72,1822 pad.0@3028,1052.5 pad.0@3037.45,104.8 pad.0@3037.45,183.49 pad.0@3067.24,512 pad.0@3067.24,572 pad.0@3088,133 pad.0@3088,183 pad.0@3123.5,909.5 pad.0@3123.5,972.5 pad.0@3123.5,1038 pad.0@3165,1823 pad.0@3175.22,1504.5 pad.0@3175.93,1620.5 pad.0@3176.93,1720 pad.998@1335,897 pad.998@1335.24,692.32 pad.998@1374.61,692.32 pad.998@1394,897 pad.998@1413.98,692.32 pad.998@1453,897 pad.998@1453.35,692.32 pad.998@1492.72,692.32 pad.998@1532.09,692.32 pad.998@1591,898 pad.998@1591.14,692.32 pad.998@1630.51,692.32 pad.998@1650,896 pad.998@1669.88,692.32 pad.998@1709,897 pad.998@1709.25,692.32 pad.998@1935,898 pad.998@1935.24,692.32 pad.998@1974.61,692.32 pad.998@1994,897 pad.998@2013.98,692.32 pad.998@2053,898 pad.998@2053.35,692.32 pad.998@2092.72,692.32 pad.998@2112,898 pad.998@2132.09,692.32 pad.998@2191,898 pad.998@2191.14,692.32 pad.998@2230.51,692.32 pad.998@2250,898 pad.998@2269.88,692.32 pad.998@2309,899 pad.998@2309.25,692.32 pad.998@2514.76,732 pad.998@2573.82,732 pad.998@2691.93,732 pad.998@2770.67,732 pad.998@2775,532 pad.998@2775,572 pad.998@2829.72,732 pad.998@2839.76,432 pad.998@2898.82,432 pad.998@2977.56,432 pad.998@3095.67,432 pad.998@3154.72,432 SW1.3 U1.1 U1.4 U1.10 U1.14 U1.17 U1.19 U1.21 U1.39 U1.41 U5.1 U5.4 U5.10 U5.14 U5.17 U5.19 U5.21 U5.39 U5.41 U9.3 U9.5 U9.7 U9.9 U9.11 U9.13 U9.16 U9.18 U9.20 U9.22 U9.27 U9.30 U9.33 U9.37 U9.40 U9.43 U9.46 U10.3 U10.5 U10.7 U10.9 U10.11 U10.13 U10.16 U10.18 U10.20 U10.22 U10.27 U10.30 U10.33 U10.37 U10.40 U10.43 U10.46 | length 7949.6
  TopLayer w10: pad.998@1335,897 U9.46@1335.24,941.61 ; U9.3@1335.24,642.39 pad.998@1335.24,692.32 ; U9.5@1374.61,642.39 pad.998@1374.61,692.32 ; pad.998@1394,897 U9.43@1394.29,941.61 ; U9.7@1413.98,642.39 pad.998@1413.98,692.32 ; pad.998@1453,897 U9.40@1453.35,941.61 ; U9.9@1453.35,642.39 pad.998@1453.35,692.32 ; U9.11@1492.72,642.39 pad.998@1492.72,692.32 ; U9.37@1512,935 1512,1029 v3(1533,1050) ; U9.13@1532.09,642.39 pad.998@1532.09,692.32 ; U9.16@1591.14,642.39 pad.998@1591.14,692.32 ; pad.998@1591.14,898 U9.33@1591.14,941.61 ; U9.18@1630.51,642.39 pad.998@1630.51,692.32 ; pad.998@1650,896 U9.30@1650.2,941.61 ; U9.20@1669.88,642.39 pad.998@1669.88,692.32 ; pad.998@1709,897 U9.27@1709.25,941.61 ; U9.22@1709.25,642.39 pad.998@1709.25,692.32 ; pad.998@1935,898 U10.46@1935.24,941.61 ; U10.3@1935.24,642.39 pad.998@1935.24,692.32 ; U10.5@1974.61,642.39 pad.998@1974.61,692.32 ; pad.998@1994,897 U10.43@1994.29,941.61 ; U10.7@2013.98,642.39 pad.998@2013.98,692.32 ; pad.998@2053,898 U10.40@2053.35,941.61 ; U10.9@2053.35,642.39 pad.998@2053.35,692.32 ; U10.11@2092.72,642.39 pad.998@2092.72,692.32 ; pad.998@2112,898 U10.37@2112.4,941.61 ; U10.13@2132.09,642.39 pad.998@2132.09,692.32 ; pad.998@2191,898 U10.33@2191.14,941.61 ; U10.16@2191.14,642.39 pad.998@2191.14,692.32 ; U10.18@2230.51,642.39 pad.998@2230.51,692.32 ; pad.998@2250,898 U10.30@2250.2,941.61 ; U10.20@2269.88,642.39 pad.998@2269.88,692.32 ; pad.998@2309,899 U10.27@2309.25,941.61 ; U10.22@2309.25,642.39 pad.998@2309.25,692.32
  TopLayer w13: U1.39@2489,872 2542.24,872 ; U1.41@2493.11,832.16 2533.23,832.16 ; pad.998@2514.76,732 U1.1@2514.76,772.12 ; pad.998@2573.82,732 U1.4@2573.82,772.12 ; pad.998@2691.93,732 U1.10@2691.93,772.12 ; pad.998@2770.67,732 U1.14@2770.67,772.12 ; 2809.39,871.53 U1.21@2849.51,871.53 ; 2814.88,832 U1.19@2855,832 ; pad.998@2829.72,732 U1.17@2829.72,772.12
  TopLayer w15: pad.0@836.11,1968.5 C114.2@874.24,1968.5 ; v3@2871,762 2897,736 C39.2@2918,736
  TopLayer w20: C35.2@2423,933 2448,933 v3(2472,909) ; C36.2@2428,736 2445,736 v3@2469,760 ; v3(2866,909) 2906,949 C40.2@2915,949 ; C39.2@2918,736 C39.2@2918,737
  TopLayer w25: P1.B4@1915.35,-33 pad.0@1915.35,183.54 ; P1.B7@2033.46,-33 pad.0@2033.46,183.54 ; pad.0@2338,184 pad.0@2338,105 2348.42,94.57 P1.B13@2348.42,-33 ; pad.0@2446.85,183.54 pad.0@2446.85,104.8 2466.53,85.11 P1.B16@2466.53,-33 ; P1.B18@2545.28,-33 pad.0@2545.28,183.54 ; pad.0@2643.7,183.54 pad.0@2643.7,104.8 2663.39,85.11 P1.B21@2663.39,-33 ; P1.B22@2702.76,-33 2702.76,85.11 pad.0@2722.44,104.8 pad.0@2722.44,183.54 ; pad.0@2801.18,183.54 pad.0@2801.18,104.8 2820.87,85.11 P1.B25@2820.87,-33 ; P1.B26@2860.24,-33 2860.24,85.11 pad.0@2879.92,104.8 pad.0@2879.92,183.54 ; pad.0@2958.66,183.54 pad.0@2958.66,104.8 2978.35,85.11 P1.B29@2978.35,-33 ; pad.0@3088,183 3087.96,82.04 3096.5,73.49 P1.B32@3096.46,-33
  BottomLayer w10: C104.2@1477,644 1492.72,659.72 pad.998@1492.72,692.32 ; C123.2@1493,988 1493,1011 v3@1533,1051 ; C121.2@2095,942 2112,925 pad.998@2112,898 ; pad.998@2132.09,692.32 2132.09,667.91 C105.2@2146,654 ; pad.998@2775,532 U5.19@2819.09,532.16 ; pad.998@2775,572 U5.21@2819.09,571.53 ; pad.998@2839.76,432 U5.17@2839.76,472.12 ; pad.998@2898.82,432 U5.14@2898.82,472.12 ; pad.998@2977.56,432 U5.10@2977.56,472.12 ; pad.998@3095.67,432 U5.4@3095.67,472.12 ; 3136.02,532.16 U5.41@3176.13,532.16 ; 3136.39,571.53 U5.39@3176.51,571.53 ; pad.998@3154.72,432 U5.1@3154.72,472.12
  BottomLayer w15: C72.2@2747,600 2747,617 v3(2760,630) ; C73.2@2747.24,467 2747.24,452.76 v3(2760,440) ; v3(3199,603) C70.2@3250,603 ; v3@3200,473 3214,459 C69.2@3252,459
  BottomLayer w20: v2@506,750 C2.2@544,750 ; v2@508,852 C2.2@552,852 ; v2(509,802) C2.2@548,802 ; v2@573,582 C1.2@606,582 ; v2@574,626 C1.2@619,626
  BottomLayer w25: P1.A4@1915.35,-33 pad.0@1915.35,144.16 ; P1.A12@2309.06,-33 2309.06,76.06 pad.0@2338,105 pad.0@2338,184 ; P1.A15@2427.16,-33 2427.16,85.11 pad.0@2446.85,104.8 pad.0@2446.85,183.54 ; P1.A18@2545.28,-33 pad.0@2545.28,183.54 ; P1.A20@2624.02,-33 2624.02,85.11 pad.0@2643.7,104.8 pad.0@2643.7,183.54 ; pad.0@2722.44,183.54 pad.0@2722.44,104.8 2742.13,85.11 P1.A23@2742.13,-33 ; P1.A24@2781.5,-33 2781.5,85.11 pad.0@2801.18,104.8 pad.0@2801.18,183.54 ; pad.0@2879.92,183.54 pad.0@2879.92,104.8 2899.61,85.11 P1.A27@2899.61,-33 ; P1.A28@2938.98,-33 2938.98,85.11 pad.0@2958.66,104.8 pad.0@2958.66,183.54 ; pad.0@3037.45,183.49 pad.0@3037.45,104.8 3057.14,85.11 P1.A31@3057.09,-33
  other v2: 3313,397 162,422 490,425 670,425 876,425 1078,425 1272,425 318,430 574,582 575,626 161,715 318,722 508,750 510,852 3294,908 162,1042 324,1049 3296,1312 162,1352 323,1356 160,1659 325,1666 3298,1872 157,1923 324,1927 156,2119 328,2126 3296,2129 3298,2386 2022,2393 2255,2395 2508,2399 2773,2399 3072,2401
  other v3: 3200.63,472.37 2468,759 2870,763
RSVD_A19: P1.A19 P2.A19 P3.A19 | length 2717.4
  MidLayer4 w7: v1(2433,1586) 2433,1379 2473,1339 2473,1194 2507,1160 2507,1059 2403,955 2403,604 2561,446 v1(2561,238)
  BottomLayer w7: v1(2433,1586) 2483,1586 2506,1609 ; v1(2561,238) 2584.65,214.35 P1.A19@2584.65,-33 ; P2.A19@2584,1311 2584,1531 2506,1609 ; P3.A19@2584.65,2112.99 2584.65,2070.65 2548,2034 2548,1996 2506,1954 2506,1609
RSVD_A32: P1.A32 P2.A32 P3.A32 | length 2520.9
  BottomLayer w7: P1.A32@3096.46,-33 3096.46,82.79 3062,117.24 3062,191.76 3088,217.76 3088,290 3183.2,385.2 3255.45,385.2 3291,420.76 3291,625 3168,748 3168,1152 3078,1242 3078,1285 3096.46,1303.46 3096.46,1726.46 3137,1767 3137,1984 3078,2043 3078,2088 3096.46,2106.46 P3.A32@3096.46,2191.73
RSVD_B3: P1.B3 P2.B3 P3.B3 | length 2125.3
  TopLayer w7: P1.B3@1875.98,-33 1875.98,60.74 1887.24,72 1887.24,202 v1(1917.24,232) ; v1(1876,1039) 1876,1214.55 1875.98,1248.98 1916,1289 1916,1335 1876,1375 P3.B3@1876,2017
  MidLayer1 w7: 1876,1047 1876,458 1917.24,416.76 v1(1917.24,232)
RSVD_B12: P1.B12 P2.B12 P3.B12 pad.998@2389,1062 | length 2928.3
  TopLayer w7: P1.B12@2304.06,-33 2302.24,-31.19 2302.24,212 2351,260.76 2351,423 2403,475 2403,1048 pad.998@2389,1062
  MidLayer2 w7: P2.B12@2304.06,1135.83 P2.B12@2309.06,1135.83 ; P3.B12@2304.06,1935.19 P3.B12@2304.06,1935.83
  BottomLayer w7: P2.B12@2309.06,1135.83 2309.06,1229.06 2324,1244 2324,1290 2272,1342 2272,1454 2307,1489 2307,1936 2341,1902 2341,1380 2388,1333 2388,1199 2353,1164 2353,1112 2389,1076 pad.998@2389,1062
  other v1: 2322.24,232
RSVD_B30: P1.B30 P2.B30 P3.B30 | length 2255.6
  TopLayer w7: P1.B30@3017.72,-33 3017.72,83.34 3005,96 3005,233 3238,466 3238,612 3079,771 3079,1074.55 P2.B30@3017.72,1135.83 3045.83,1135.83 3099,1189 3099,1223 3080,1242 3080,1289 3092,1301 3092,1337 3063,1366 3063,1890.55 P3.B30@3017.72,1935.83
S0_JTAG1: P2.B9 U9.28 | length 648.2
  TopLayer w7: U9.28@1689.57,941.61 v1(1689.57,1027) ; v1(1918,1061) 2065.2,1061 2112.2,1108 P2.B9@2112.21,1214.57
  BottomLayer w7: v1(1689.57,1027) 1723.57,1061 v1(1918,1061)
S0_JTAG2: P2.A5 U9.41 | length 928.2
  TopLayer w7: U9.41@1433.66,941.61 v1@1433.66,1314.66
  BottomLayer w7: v1(1434,1314) 1588,1314 1629,1355 1912.72,1355 P2.A5@1954.72,1312.99
S0_JTAG3: P2.A6 U9.35 | length 913.5
  TopLayer w7: U9.35@1551.77,941.61 1551.77,989.77 1574,1012 1574,1370 v1(1571,1373)
  BottomLayer w7: v1(1571,1373) 1639,1441 1944.83,1441 P2.A6@1994.09,1391.73
S0_JTAG4: P2.A7 U9.34 | length 755.7
  TopLayer w7: U9.34@1571.46,941.61 1571.46,987.46 1595,1011 v1@1595,1094 ; v1@1933,1102 1952.24,1121.24 1952.24,1152 1992.24,1192 1992.24,1271.78 P2.A7@2033.46,1312.99
  BottomLayer w7: v1@1595,1094 1599,1098 1930,1098 v1(1933,1101)
  other v1: 1595,1093
S0_JTAG5: P2.A8 U9.29 | length 790.6
  TopLayer w7: U9.29@1669.88,941.61 v1(1669.88,1047) ; v1(1916,1081) 2000.24,1081 2032.24,1113 2032.24,1157 2072.83,1197.59 P2.A8@2072.84,1391.73
  BottomLayer w7: v1(1669.88,1047) 1703.88,1081 v1(1916,1081)
S0_PERN0: P2.A17 U5.27 | length 1102.4
  BottomLayer w4: 2472.5,1249 2472.5,1332 2483.5,1343 2495.5,1343 2505.91,1332.59 P2.A17@2505.91,1312.99 ; 2935,661 2935.24,660.76 2935.24,654 2938.19,651.06 U5.27@2938.19,611.88
  BottomLayer w6: 2472.5,1249 2472.5,1198 2473.5,1197 ; 2511.5,1159 2511.5,1096.5 2513,1095
  BottomLayer w6.5: 2473.5,1197 2511.5,1159 ; 2513,1095 2588.5,1019.5 2804.5,1019.5 2935,889 2935,661 ; U5.27@2938.19,611.88 U5.27@2938.19,612.87
S0_PERN1: P2.A22 U5.29 | length 936.7
  BottomLayer w4: P2.A22@2702.76,1391.73 2708.5,1386 2708.5,1250 ; 2974.11,663.89 2974.11,656 2977.56,652.56 U5.29@2977.56,615
  BottomLayer w6: 2708.5,1250 2708.5,1196 2709.5,1195 ; 2748,1156.5 2748,1099 2749,1098
  BottomLayer w6.5: 2709.5,1195 2748,1156.5 ; 2749,1098 2782,1065 2855.5,1065 2974,946.5 2974,663.89 ; U5.29@2977.56,611.88 U5.29@2977.56,615
S0_PERN2: P2.A26 U5.36 | length 887.3
  BottomLayer w4: P2.A26@2860.24,1391.73 2866,1385.98 2866,1250 ; 3112,664 3112,654 3115,651 U5.36@3115,610
  BottomLayer w6: 2866,1250 2866,1199 2867,1198 ; 2905.5,1159.5 2905.5,1112.5 2906.5,1111.5
  BottomLayer w6.5: 2867,1198 2905.5,1159.5 ; 2906.5,1111.5 3041.5,976.5 3041.5,764 3112,693.5 3112,664
S0_PERN3: P2.A30 U5.38 | length 836.6
  BottomLayer w4: P2.A30@3017.72,1391.73 3023.5,1385.96 3023.5,1250 ; 3152,665 3152,656 3154.72,653.28 U5.38@3154.72,613
  BottomLayer w6: 3023.5,1250 3023.5,1199.5 3025,1198 ; 3063,1160 3063,1094 3064,1093
  BottomLayer w6.5: 3025,1198 3063,1160 ; 3064,1093 3091,1066 3091,774 3152,713 3152,665 ; U5.38@3154.72,611.88 U5.38@3154.72,613
S0_PERP0: P2.A16 U5.26 | length 1101.1
  BottomLayer w4: 2460.5,1249 2460.5,1385.7 P2.A16@2466.54,1391.73 ; U5.26@2918.5,614 2918.5,651 2921.5,654 2921.5,661
  BottomLayer w6: 2460.5,1191 2460.5,1249 ; 2498.5,1153 2499.5,1152 2499.5,1089.5
  BottomLayer w6.5: 2460.5,1191 2498.5,1153 ; 2499.5,1089.5 2583,1006 2799,1006 2921.5,883.5 2921.5,661 ; U5.26@2918.5,611.88 U5.26@2918.5,614
S0_PERP1: P2.A21 U5.28 | length 933.7
  BottomLayer w4: P2.A21@2663.39,1312.99 2663.39,1330.39 2675,1342 2687.5,1342 2696.5,1333 2696.5,1250 ; U5.28@2957.87,614 2957.87,652.37 2960.5,655 2960.5,664
  BottomLayer w6: 2696.5,1189 2696.5,1250 ; 2735,1150.5 2736,1149.5 2736,1092
  BottomLayer w6.5: 2696.5,1189 2735,1150.5 ; 2736,1092 2777,1051 2850.5,1051 2960.5,941 2960.5,664 ; U5.28@2957.87,611.88 U5.28@2957.87,614
S0_PERP2: P2.A25 U5.35 | length 889.3
  BottomLayer w4: P2.A25@2820.87,1312.99 2820.87,1333.62 2831.74,1344.5 2844.5,1344.5 2854,1335 2854,1250 ; U5.35@3095,615 3095,650.5 3098.5,654 3098.5,664
  BottomLayer w6: 2854,1192 2854,1250 ; 2892.5,1153.5 2893.5,1152.5 2893,1105.5
  BottomLayer w6.5: 2854,1192 2892.5,1153.5 ; 2893,1105.5 3028,971 3028,758.5 3098.5,688 3098.5,664 ; U5.35@3095,611 U5.35@3095,615
S0_PERP3: P2.A29 U5.37 | length 838
  BottomLayer w4: P2.A29@2978.35,1312.99 2978.35,1333.85 2988.5,1344 3000,1344 3011.5,1332.5 3011.5,1250 ; U5.37@3134.8,612.87 3135.5,613.57 3135.5,652 3138.5,655 3138.5,665
  BottomLayer w6: 3011.5,1192.5 3011.5,1250 ; 3050,1154 3051,1153 3051,1086.5
  BottomLayer w6.5: 3011.5,1192.5 3050,1154 ; 3051,1086.5 3077.5,1060 3077.5,768.5 3138.5,707.5 3138.5,665 ; U5.37@3135.04,611.88 U5.37@3135.04,613.11
S0_PERST#: P2.A11 U10.47 | length 689.7
  TopLayer w7: U10.47@1915.55,941.61 1915.55,1007.55 1940,1032 2100,1032 2126,1058 2163,1058 2230,1125 v1(2230,1153)
  BottomLayer w7: P2.A11@2190.95,1312.99 2151,1273.05 2151,1192 2190,1153 v1(2230,1153)
S0_PETN0: P2.B15 U1.37 | length 346.8
  TopLayer w4: P2.B15@2426.86,1214.17 2433,1208.04 2433,1119 ; 2531.5,963 2531.5,954.5 2534.45,951.55 U1.37@2534.45,912
  TopLayer w6: 2433,1119 2433,1105 2434,1104
  TopLayer w6.5: P2.B15@2427.17,1214.57 P2.B15@2427.21,1214.53 ; 2434,1104 2531.5,1006.5 2531.5,963
S0_PETN1: P2.B20 U1.35 | length 315.3
  TopLayer w4: 2570.5,962 2570.5,954.5 2574,951 2574,916.08 U1.35@2573.87,915.95 ; 2590.5,1115 2590.5,1152 2602.5,1164 2615,1164 2623.72,1155.28 P2.B20@2623.72,1135.43
  TopLayer w6: 2590.5,1078.5 2590.5,1115
  TopLayer w6.5: 2570.5,962 2570.5,1058.5 2590.5,1078.5 ; U1.35@2573.82,908.14 U1.35@2573.82,912.87 U1.35@2573.87,915.95
S0_PETN2: P2.B24 U1.28 | length 320.1
  TopLayer w4: 2708.64,967 2708.64,957.61 2711.62,954.63 U1.28@2711.62,916.61 ; 2748,1113 2748,1154.5 2756.5,1163 2774,1163 2781.5,1155.5 P2.B24@2781.5,1138
  TopLayer w6: 2748,1071 2748,1113
  TopLayer w6.5: 2708.64,967 2708.64,1031.64 2748,1071 ; U1.28@2711.61,908.14 U1.28@2711.61,912.87 U1.28@2711.6,913.02 ; P2.B24@2781.5,1135.83 P2.B24@2781.5,1138
S0_PETN3: P2.B28 U1.26 | length 421.7
  TopLayer w4: 2748,966 2748,957 2750.98,954.02 U1.26@2750.98,916 ; 2905.5,1115 2905.5,1159 2912.5,1166 2926,1166 2938.98,1153.02 P2.B28@2938.98,1138
  TopLayer w6: 2905.5,1088 2905.5,1115
  TopLayer w6.5: 2748,966 2748,1008 2765,1025 2842.5,1025 2905.5,1088 ; U1.26@2750.98,908.14 U1.26@2750.98,916 ; P2.B28@2938.98,1135.83 P2.B28@2938.98,1138
S0_PETP0: P2.B14 U1.38 | length 352.3
  TopLayer w4: P2.B14@2387.49,1135.43 2387.49,1156.49 2397,1166 2411.5,1166 2421,1156.5 2421,1119 ; U1.38@2514.76,915 2514.76,950.76 2518,954 2518,962
  TopLayer w6: 2421,1098 2421,1119
  TopLayer w6.5: 2421,1098 2518,1001 2518,962 ; U1.38@2514.76,908.14 U1.38@2514.76,915
S0_PETP1: P2.B19 U1.36 | length 319.6
  TopLayer w4: U1.36@2554.11,913.72 2554.11,951.11 2557,954 2557,962 ; 2578.5,1115 2578.5,1208.43 P2.B19@2584.65,1214.57
  TopLayer w6: 2577.5,1084.5 2578.5,1085.5 2578.5,1115
  TopLayer w6.5: U1.36@2554.11,913.72 U1.36@2554.13,912.87 U1.36@2554.13,908.14 ; 2557,962 2557,1064 2577.5,1084.5 ; P2.B19@2584.29,1214.23 P2.B19@2584.65,1214.57
S0_PETP2: P2.B23 U1.29 | length 328
  TopLayer w4: U1.29@2691.94,912.61 2691.94,954.41 2695.21,957.68 2695.21,967 ; 2736,1114 2736,1208.45 P2.B23@2742.13,1214.57
  TopLayer w6: 2735,1077 2736,1078 2736,1114
  TopLayer w6.5: U1.29@2691.93,908.14 2691.94,912.61 U1.29@2691.93,912.87 ; 2695.21,967 2695.21,1037.21 2735,1077 ; P2.B23@2741.76,1214.24 P2.B23@2742.13,1214.57
S0_PETP3: P2.B27 U1.27 | length 422.9
  TopLayer w4: U1.27@2731.3,912 2731.3,953.8 2734.5,957 2734.5,964 ; 2893.5,1115 2893.5,1208.47 P2.B27@2899.61,1214.57
  TopLayer w6: 2892.5,1094 2893.5,1095 2893.5,1115
  TopLayer w6.5: U1.27@2731.3,908.14 U1.27@2731.3,912.87 ; 2734.5,964 2734.5,1013.5 2759.5,1038.5 2837,1038.5 2892.5,1094 ; P2.B27@2899.27,1214.21 P2.B27@2899.61,1214.57
S0_PRSNT1#: P2.A1 U9.48 | length 855.7
  TopLayer w7: U9.48@1295.87,941.61 v1@1295.87,1284
  BottomLayer w7: v1(1296,1284) 1608,1284 1637,1313 P2.A1@1797.24,1312.99
S0_PRSNT2#: P2.B17 U10.35 | length 553.4
  TopLayer w4: U10.35@2151.77,941.61 v1(2151.77,991.53)
  TopLayer w7: v1(2480,1088) 2505.91,1112.91 P2.B17@2505.91,1211.91
  MidLayer1 w4: v1(2151.77,991.53) 2191.5,1031.5 2219.5,1031.5
  MidLayer1 w7: 2219.5,1031.5 2424.5,1031.5 v1(2480,1088)
S0_PRSNT3#: P2.B31 U10.34 | length 1177.1
  TopLayer w4: U10.34@2171,941 2171,986
  TopLayer w7: U10.34@2171,941 2171,995 2188,1012 2281,1012 2353.5,1084.5 2353.5,1151.5 2390,1188 2390,1235 2411,1256 3015.48,1256 P2.B31@3057.09,1214.57
S0_REFCLK+: P2.A13 pad.9 U10.42 | length 763.5
  TopLayer w7.5: U10.42@2013.98,941.61 pad.9@2013.98,991.53
  MidLayer1 w4: P2.A13@2348.43,1312.99 2348.42,1336.18 2357.24,1345 2370,1345 2379.5,1335.5 2379.5,1261
  MidLayer1 w6.5: pad.9@2013.98,991.53 pad.9@2015.74,993.29 ; pad.9@2016,993.5 2016,1038 2056,1078 2323.5,1078 2340.5,1095 2340.5,1158 2379.5,1197 2379.5,1261
S0_REFCLK-: P2.A14 pad.10 U10.41 | length 761.3
  TopLayer w7.5: U10.41@2033.66,941.61 pad.10@2033.66,991.53
  MidLayer1 w4: P2.A14@2387.8,1391.73 2395,1384.53 2395,1262
  MidLayer1 w6.5: pad.10@2033.66,991.53 2031.5,993.5 2031.5,1031.5 2062.5,1062.5 2330,1062.5 2356,1088.5 2356,1151.5 2395,1190.5 2395,1262
S0_SMCLK: P2.B5 U9.47 | length 956.4
  TopLayer w7: U9.47@1315.55,941.61 v1@1315.55,1220.55
  BottomLayer w7: v1(1315,1220) 1639,1220 1680,1261 1909,1261 P2.B5@1956,1214
S0_SMDAT: P2.B6 U9.42 | length 807.1
  TopLayer w7: U9.42@1413.98,941.61 v1@1413.98,1137.02
  BottomLayer w7: v1(1414,1136) 1565,1136 1603,1174 1955.92,1174 P2.B6@1994.09,1135.83
S0_WAKE#: P2.B11 U10.48 | length 508.2
  TopLayer w7: U10.48@1895.87,941.61 1895.87,1010.87 1930.12,1045.12 2088.12,1045.12 2131,1088 2165.94,1088 2190.94,1113 P2.B11@2190.95,1214.57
